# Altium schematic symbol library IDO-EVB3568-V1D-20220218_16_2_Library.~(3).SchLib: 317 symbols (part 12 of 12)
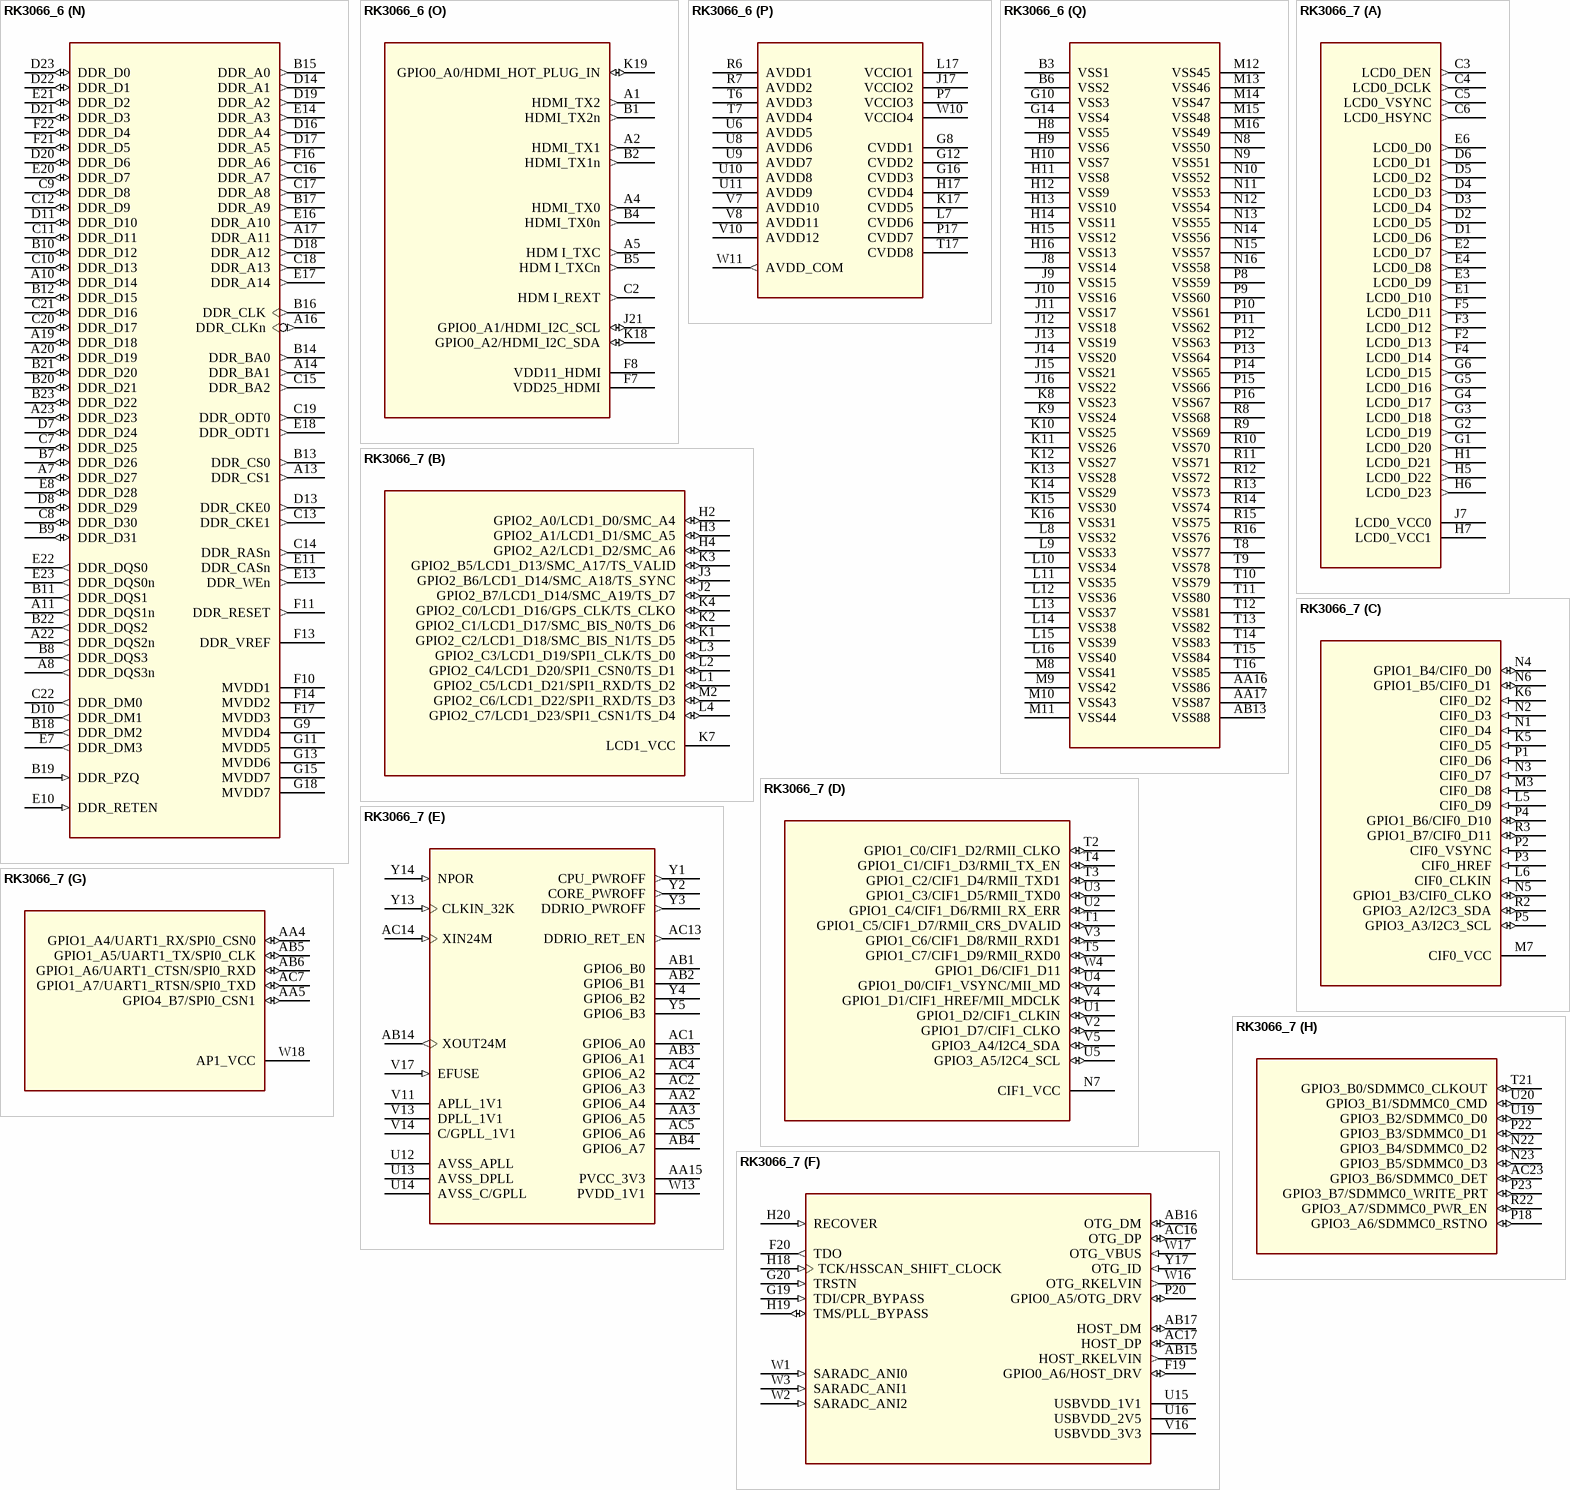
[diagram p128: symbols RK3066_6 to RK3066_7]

## RK3066_6
designator U?
Altium-Right: 160; Altium-Bottom: 120; Altium-Bottom1: 130; Altium-Bottom2: 280; Altium-Right3: 180; Altium-Bottom3: 310; Altium-Bottom4: 270; Altium-Bottom5: 140; Altium-Bottom6: 230; Altium-Bottom7: 530; Altium-Right8: 150; Altium-Bottom8: 250; Altium-Right9: 110; Altium-Bottom9: 170; Altium-Right10: 100; Altium-Bottom10: 470; Altium-Right11: 80; Altium-Bottom11: 350; Altium-Right12: 200; Altium-Bottom12: 190
footprint BGA453
part A pins: C3 LCD0_DEN (out), C4 LCD0_DCLK (out), C5 LCD0_VSYNC (out), C6 LCD0_HSYNC (out), D1 LCD0_D6 (out), D2 LCD0_D5 (out), D3 LCD0_D4 (out), D4 LCD0_D3 (out), D5 LCD0_D2 (out), D6 LCD0_D1 (out), E1 LCD0_D10 (out), E2 LCD0_D7 (out), E3 LCD0_D9 (out), E4 LCD0_D8 (out), E6 LCD0_D0 (out), F2 LCD0_D13 (out), F3 LCD0_D12 (out), F4 LCD0_D14 (out), F5 LCD0_D11 (out), G1 LCD0_D20 (out), G2 LCD0_D19 (out), G3 LCD0_D18 (out), G4 LCD0_D17 (out), G5 LCD0_D16 (out), G6 LCD0_D15 (out), H1 LCD0_D21 (out), H5 LCD0_D22 (out), H6 LCD0_D23 (out), H7 LCD0_VCC1 (power), J7 LCD0_VCC0 (power)
part B pins: H2 GPIO2_A0/LCD1_D0/SMC_A4 (io), H3 GPIO2_A1/LCD1_D1/SMC_A5 (io), H4 GPIO2_A2/LCD1_D2/SMC_A6 (io), J2 GPIO2_B7/LCD1_D14/SMC_A19/TS_D7 (io), J3 GPIO2_B6/LCD1_D14/SMC_A18/TS_SYNC (io), K1 GPIO2_C2/LCD1_D18/SMC_BIS_N1/TS_D5 (io), K2 GPIO2_C1/LCD1_D17/SMC_BIS_N0/TS_D6 (io), K3 GPIO2_B5/LCD1_D13/SMC_A17/TS_VALID (io), K4 GPIO2_C0/LCD1_D16/GPS_CLK/TS_CLKO (io), K7 LCD1_VCC (power), L1 GPIO2_C5/LCD1_D21/SPI1_RXD/TS_D2 (io), L2 GPIO2_C4/LCD1_D20/SPI1_CSN0/TS_D1 (io), L3 GPIO2_C3/LCD1_D19/SPI1_CLK/TS_D0 (io), L4 GPIO2_C7/LCD1_D23/SPI1_CSN1/TS_D4 (io), M2 GPIO2_C6/LCD1_D22/SPI1_RXD/TS_D3 (io)
part C pins: K5 CIF0_D5 (in), K6 CIF0_D2 (in), L5 CIF0_D9 (in), L6 CIF0_CLKIN (in), M3 CIF0_D8 (in), M7 CIF0_VCC (power), N1 CIF0_D4 (in), N2 CIF0_D3 (in), N3 CIF0_D7 (in), N4 GPIO1_B4/CIF0_D0 (io), N5 GPIO1_B3/CIF0_CLKO (io), N6 GPIO1_B5/CIF0_D1 (io), P1 CIF0_D6 (in), P2 CIF0_VSYNC (in), P3 CIF0_HREF (in), P4 GPIO1_B6/CIF0_D10 (io), P5 GPIO3_A3/I2C3_SCL (io), R2 GPIO3_A2/I2C3_SDA (io), R3 GPIO1_B7/CIF0_D11 (io)
part D pins: N7 CIF1_VCC (power), T1 GPIO1_C5/CIF1_D7/RMII_CRS_DVALID (io), T2 GPIO1_C0/CIF1_D2/RMII_CLKO (io), T3 GPIO1_C2/CIF1_D4/RMII_TXD1 (io), T4 GPIO1_C1/CIF1_D3/RMII_TX_EN (io), T5 GPIO1_C7/CIF1_D9/RMII_RXD0 (io), U1 GPIO1_D2/CIF1_CLKIN (io), U2 GPIO1_C4/CIF1_D6/RMII_RX_ERR (io), U3 GPIO1_C3/CIF1_D5/RMII_TXD0 (io), U4 GPIO1_D0/CIF1_VSYNC/MII_MD (io), U5 GPIO3_A5/I2C4_SCL (io), V2 GPIO1_D7/CIF1_CLKO (io), V3 GPIO1_C6/CIF1_D8/RMII_RXD1 (io), V4 GPIO1_D1/CIF1_HREF/MII_MDCLK (io), V5 GPIO3_A4/I2C4_SDA (io), W4 GPIO1_D6/CIF1_D11 (io)
part E pins: AA2 GPIO6_A4, AA3 GPIO6_A5, AA15 PVCC_3V3 (power), AB1 GPIO6_B0, AB2 GPIO6_B1, AB3 GPIO6_A1, AB4 GPIO6_A7, AB14 XOUT24M (out), AC1 GPIO6_A0, AC2 GPIO6_A3, AC4 GPIO6_A2, AC5 GPIO6_A6, AC13 DDRIO_RET_EN (out), AC14 XIN24M (in), U12 AVSS_APLL (power), U13 AVSS_DPLL (power), U14 AVSS_C/GPLL (power), V11 APLL_1V1 (power), V13 DPLL_1V1 (power), V14 C/GPLL_1V1 (power), V17 EFUSE (in), W13 PVDD_1V1 (power), Y1 CPU_PWROFF (out), Y2 CORE_PWROFF (out), Y3 DDRIO_PWROFF (out), Y4 GPIO6_B2, Y5 GPIO6_B3, Y13 CLKIN_32K (in), Y14 NPOR (in)
part F pins: AB15 HOST_RKELVIN (out), AB16 OTG_DM (io), AB17 HOST_DM (io), AC16 OTG_DP (io), AC17 HOST_DP (io), F19 GPIO0_A6/HOST_DRV (io), F20 TDO (out), G19 TDI/CPR_BYPASS (in), G20 TRSTN (in), H18 TCK/HSSCAN_SHIFT_CLOCK (in), H19 TMS/PLL_BYPASS (io), H20 RECOVER (in), P20 GPIO0_A5/OTG_DRV (io), U15 USBVDD_1V1 (power), U16 USBVDD_2V5 (power), V16 USBVDD_3V3 (power), W1 SARADC_ANI0 (in), W2 SARADC_ANI2 (in), W3 SARADC_ANI1 (in), W16 OTG_RKELVIN (out), W17 OTG_VBUS (in), Y17 OTG_ID (in)
part G pins: AA4 GPIO1_A4/UART1_RX/SPI0_CSN0 (io), AA5 GPIO4_B7/SPI0_CSN1 (io), AB5 GPIO1_A5/UART1_TX/SPI0_CLK (io), AB6 GPIO1_A6/UART1_CTSN/SPI0_RXD (io), AC7 GPIO1_A7/UART1_RTSN/SPI0_TXD (io), W18 AP1_VCC (power)
part H pins: AC23 GPIO3_B6/SDMMC0_DET (io), N22 GPIO3_B4/SDMMC0_D2 (io), N23 GPIO3_B5/SDMMC0_D3 (io), P18 GPIO3_A6/SDMMC0_RSTNO (io), P22 GPIO3_B3/SDMMC0_D1 (io), P23 GPIO3_B7/SDMMC0_WRITE_PRT (io), R22 GPIO3_A7/SDMMC0_PWR_EN (io), T21 GPIO3_B0/SDMMC0_CLKOUT (io), U19 GPIO3_B2/SDMMC0_D0 (io), U20 GPIO3_B1/SDMMC0_CMD (io)
part I pins: AA6 GPIO3_C1/SDMMC1_D0 (io), AA7 GPIO3_C2/SDMMC1_D1 (io), AA8 GPIO3_C7/SDMMC1_WRITE_PRT (io), AA9 GPIO1_A1/UART0_SOUT (io), AA10 GPIO0_C3/I2S1_LRCK_TX (io), AA12 GPIO1_A0/UART0_SIN (io), AB7 GPIO3_C0/SDMMC1_CMD (io), AB8 GPIO3_D2/SDMMC1_INT (io), AB9 GPIO0_C1/I2S1_SCLK (io), AB10 GPIO3_D1/SDMMC1_BACKEND (io), AB11 GPIO1_A2/UART0_CTS (io), AC8 GPIO3_C4/SDMMC1_D3 (io), AC10 GPIO3_C3/SDMMC1_D2 (io), AC11 GPIO0_C2/I2S1_LRCK_RX (io), U18 AP0_VCC (power), W6 GPIO3_C6/SDMMC1_DET (io), W7 GPIO0_C4/I2S1_SDI (io), W8 GPIO1_A3/UART0_RTS (io), Y6 GPIO3_C5/SDMMC1_CLKO (io), Y7 GPIO3_D0/SDMMC1_PWR_EN (io), Y8 GPIO0_C5/I2S1_SDO (io), Y11 GPIO0_C0/I2S1_CLK (io)
part J pins: AA11 GPIO4_C0/SMC_D0/TRACE_D0 (io), AA13 GPIO4_C4/SMC_D4/TRACE_D4 (io), AA14 GPIO4_D0/SMC_D8/TRACE_D8 (io), AA18 GPIO4_D3/SMC_D11/TRACE_D11 (io), AA19 GPIO4_D1/SMC_D9/TRACE_D9 (io), AA20 GPIO4_D5/SMC_D13/TRACE_D13 (io), AA21 GPIO0_D5/I2S2_SDO/SMC_A1 (io), AA22 GPIO0_D4/I2S2_SDI/SMC_A0 (io), AB12 GPIO4_C6/SMC_D6/TRACE_D6 (io), AB18 GPIO4_C3/SMC_D3/TRACE_D3 (io), AB19 GPIO4_D6/SMC_D14/TRACE_D14 (io), AB20 GPIO0_C7/SMC_A3/TRACE_CTL (io), AB21 GPIO0_D2/I2S2_LRCK_RX/SMC_OEN (io), AB23 GPIO0_C6/SMC_A2/TRACE_CLK (io), AC19 GPIO4_D7/SMC_D15/TRACE_D15 (io), AC20 GPIO4_D4/SMC_D12/TRACE_D12 (io), AC22 GPIO0_D3/I2S2_LRCK_TX/SMC_ADVN (io), R17 SMC_VCC (power), W14 GPIO4_C7/SMC_D7/TRACE_D7 (io), Y10 GPIO4_C1/SMC_D1/TRACE_D1 (io), Y16 GPIO4_C2/SMC_D2/TRACE_D2 (io), Y18 GPIO4_C5/SMC_D5/TRACE_D5 (io), Y19 GPIO4_D2/SMC_D10/TRACE_D10 (io), Y20 GPIO0_D1/I2S2_SCLK/SMC_WEN (io), Y23 GPIO0_D0/I2S2_CLK/SMC_CSN0 (io)
part K pins: AB22 FLASH_D0/EMMC_D0 (io), M17 FLASH_VCC0 (power), N17 FLASH_VCC1 (power), T18 GPIO4_B0/FLASH_CS1 (io), T19 GPIO4_B1/FLASH_CS2/EMMC_CMD (io), T20 GPIO4_B2/FLASH_CS3/EMMC_RST (io), T22 FLASH_ALE (out), T23 FLASH_CS0 (out), U21 FLASH_WP/EMMC_PWR_EN (out), U22 FLASH_D7/EMMC_D7 (io), U23 FLASH_D6/EMMC_D6 (io), V19 FLASH_RDN (out), V20 FLASH_CLE (out), V21 FLASH_RDY (out), V22 FLASH_D5/EMMC_D5 (io), W20 FLASH_WRN (out), W21 GPIO3_D7/FLASH_DQS/EMMC_CLKO (io), W22 FLASH_D4/EMMC_D4 (io), W23 FLASH_D3/EMMC_D3 (io), Y21 FLASH_D1/EMMC_D1 (io), Y22 FLASH_D2/EMMC_D2 (io)
part L pins: L18 GPIO0_B4/I2S0_D0 (io), L19 GPIO0_B7/I2S0_D3 (io), L21 GPIO1_B2/SPDIF_TX (io), L22 GPIO0_B5/I2S0_D1 (io), N18 GPIO0_B6/I2S0_D2 (io), N20 GPIO0_B2/I2S0_LRCK_RX (io), N21 GPIO0_B1/I2S0_SCLK (io), P19 GPIO0_A7/I2S0_SDI (io), P21 GPIO0_B3/I2S0_LRCK_TX (io), R21 GPIO0_B0/I2S0_CLK (io)
part M pins: G21 GPIO0_A3/PWM0 (io), G22 GPIO0_D6/PWM2 (io), G23 GPIO0_A4/PWM1 (io), H21 GPIO0_D7/PWM3 (io), H22 GPIO3_A1/I2C2_SCL (io), H23 GPIO2_D4/I2C0_SDA (io), J22 GPIO2_D5/I2C0_SCL (io), K20 GPIO3_D6/UART3_RTS (io), K21 GPIO3_D4/UART3_SOUT (io), K22 GPIO3_D3/UART3_SIN (io), K23 GPIO2_D6/I2C1_SDA (io), L20 GPIO3_D5/UART3_CTS (io), L23 GPIO1_B1/UART2_SOUT (io), M21 GPIO2_D7/I2C1_SCL (io), M22 GPIO1_B0/UART2_SIN (io), N19 GPIO3_A0/I2C2_SDA (io)
part N pins: A7 DDR_D27 (io), A8 DDR_DQS3n (out), A10 DDR_D14 (io), A11 DDR_DQS1n (out), A13 DDR_CS1 (out), A14 DDR_BA1 (out), A16 DDR_CLKn (out), A17 DDR_A11 (out), A19 DDR_D18 (io), A20 DDR_D19 (io), A22 DDR_DQS2n (out), A23 DDR_D23 (io), B7 DDR_D26 (io), B8 DDR_DQS3 (out), B9 DDR_D31 (io), B10 DDR_D12 (io), B11 DDR_DQS1 (out), B12 DDR_D15 (io), B13 DDR_CS0 (out), B14 DDR_BA0 (out), B15 DDR_A0 (out), B16 DDR_CLK (out), B17 DDR_A9 (out), B18 DDR_DM2 (out), B19 DDR_PZQ (in), B20 DDR_D21 (io), B21 DDR_D20 (io), B22 DDR_DQS2 (out), B23 DDR_D22 (io), C7 DDR_D25 (io), C8 DDR_D30 (io), C9 DDR_D8 (io), C10 DDR_D13 (io), C11 DDR_D11 (io), C12 DDR_D9 (io), C13 DDR_CKE1 (out), C14 DDR_RASn (out), C15 DDR_BA2 (out), C16 DDR_A7 (out), C17 DDR_A8 (out), C18 DDR_A13 (out), C19 DDR_ODT0 (out), C20 DDR_D17 (io), C21 DDR_D16 (io), C22 DDR_DM0 (out), D7 DDR_D24 (io), D8 DDR_D29 (io), D10 DDR_DM1 (out), D11 DDR_D10 (io), D13 DDR_CKE0 (out), D14 DDR_A1 (out), D16 DDR_A4 (out), D17 DDR_A5 (out), D18 DDR_A12 (out), D19 DDR_A2 (out), D20 DDR_D6 (io), D21 DDR_D3 (io), D22 DDR_D1 (io), D23 DDR_D0 (io), E7 DDR_DM3 (out), E8 DDR_D28 (io), E10 DDR_RETEN (in), E11 DDR_CASn (out), E13 DDR_WEn (out), E14 DDR_A3 (out), E16 DDR_A10 (out), E17 DDR_A14 (out), E18 DDR_ODT1 (out), E20 DDR_D7 (io), E21 DDR_D2 (io), E22 DDR_DQS0 (out), E23 DDR_DQS0n (out), F10 MVDD1 (power), F11 DDR_RESET (out), F13 DDR_VREF (power), F14 MVDD2 (power), F16 DDR_A6 (out), F17 MVDD3 (power), F21 DDR_D5 (io), F22 DDR_D4 (io), G9 MVDD4 (power), G11 MVDD5 (power), G13 MVDD6 (power), G15 MVDD7 (power), G18 MVDD7 (power)
part O pins: A1 HDMI_TX2 (out), A2 HDMI_TX1 (out), A4 HDMI_TX0 (out), A5 HDM I_TXC (out), B1 HDMI_TX2n (out), B2 HDMI_TX1n (out), B4 HDMI_TX0n (out), B5 HDM I_TXCn (out), C2 HDM I_REXT (out), F7 VDD25_HDMI (power), F8 VDD11_HDMI (power), J21 GPIO0_A1/HDMI_I2C_SCL (io), K18 GPIO0_A2/HDMI_I2C_SDA (io), K19 GPIO0_A0/HDMI_HOT_PLUG_IN (io)
part P pins: G8 CVDD1 (power), G12 CVDD2 (power), G16 CVDD3 (power), H17 CVDD4 (power), J17 VCCIO2 (power), K17 CVDD5 (power), L7 CVDD6 (power), L17 VCCIO1 (power), P7 VCCIO3 (power), P17 CVDD7 (power), R6 AVDD1 (power), R7 AVDD2 (power), T6 AVDD3 (power), T7 AVDD4 (power), T17 CVDD8 (power), U6 AVDD5 (power), U8 AVDD6 (power), U9 AVDD7 (power), U10 AVDD8 (power), U11 AVDD9 (power), V7 AVDD10 (power), V8 AVDD11 (power), V10 AVDD12 (power), W10 VCCIO4 (power), W11 AVDD_COM (out)
part Q pins: AA16 VSS86 (power), AA17 VSS87 (power), AB13 VSS88 (power), B3 VSS1 (power), B6 VSS2 (power), G10 VSS3 (power), G14 VSS4 (power), H8 VSS5 (power), H9 VSS6 (power), H10 VSS7 (power), H11 VSS8 (power), H12 VSS9 (power), H13 VSS10 (power), H14 VSS11 (power), H15 VSS12 (power), H16 VSS13 (power), J8 VSS14 (power), J9 VSS15 (power), J10 VSS16 (power), J11 VSS17 (power), J12 VSS18 (power), J13 VSS19 (power), J14 VSS20 (power), J15 VSS21 (power), J16 VSS22 (power), K8 VSS23 (power), K9 VSS24 (power), K10 VSS25 (power), K11 VSS26 (power), K12 VSS27 (power), K13 VSS28 (power), K14 VSS29 (power), K15 VSS30 (power), K16 VSS31 (power), L8 VSS32 (power), L9 VSS33 (power), L10 VSS34 (power), L11 VSS35 (power), L12 VSS36 (power), L13 VSS37 (power), L14 VSS38 (power), L15 VSS39 (power), L16 VSS40 (power), M8 VSS41 (power), M9 VSS42 (power), M10 VSS43 (power), M11 VSS44 (power), M12 VSS45 (power), M13 VSS46 (power), M14 VSS47 (power), M15 VSS48 (power), M16 VSS49 (power), N8 VSS50 (power), N9 VSS51 (power), N10 VSS52 (power), N11 VSS53 (power), N12 VSS54 (power), N13 VSS55 (power), N14 VSS56 (power), N15 VSS57 (power), N16 VSS58 (power), P8 VSS59 (power), P9 VSS60 (power), P10 VSS61 (power), P11 VSS62 (power), P12 VSS63 (power), P13 VSS64 (power), P14 VSS65 (power), P15 VSS66 (power), P16 VSS67 (power), R8 VSS68 (power), R9 VSS69 (power), R10 VSS70 (power), R11 VSS71 (power), R12 VSS72 (power), R13 VSS73 (power), R14 VSS74 (power), R15 VSS75 (power), R16 VSS76 (power), T8 VSS77 (power), T9 VSS78 (power), T10 VSS79 (power), T11 VSS80 (power), T12 VSS81 (power), T13 VSS82 (power), T14 VSS83 (power), T15 VSS84 (power), T16 VSS85 (power)

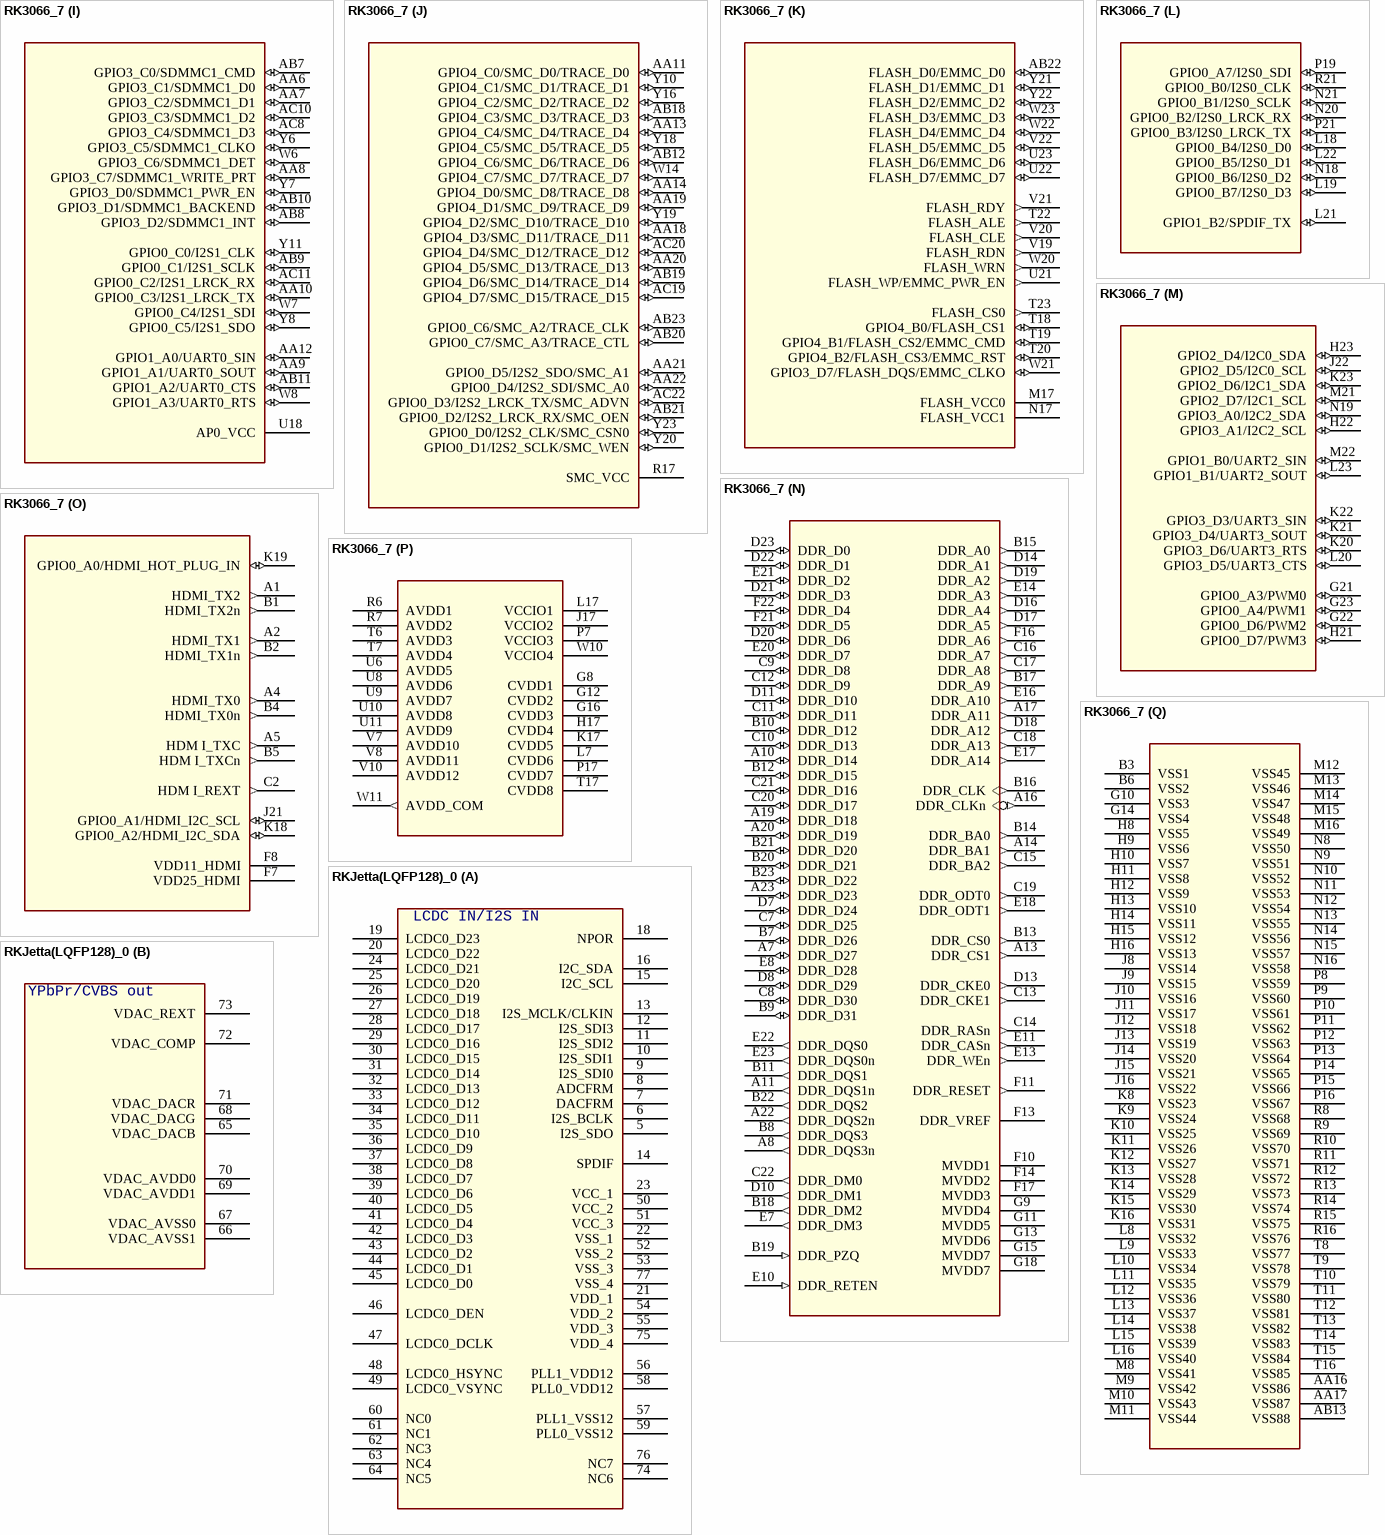
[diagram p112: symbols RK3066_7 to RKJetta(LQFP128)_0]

## RK3066_7
designator U?
Altium-Right: 160; Altium-Bottom: 130; Altium-Bottom1: 280; Altium-Right2: 180; Altium-Bottom2: 310; Altium-Bottom3: 270; Altium-Right4: 120; Altium-Bottom4: 140; Altium-Bottom5: 230; Altium-Bottom6: 530; Altium-Right7: 150; Altium-Bottom7: 250; Altium-Right8: 110; Altium-Bottom8: 170; Altium-Right9: 100; Altium-Bottom9: 470; Altium-Right10: 80; Altium-Bottom10: 350; Altium-Right11: 200; Altium-Bottom11: 190
footprint BGA453
part A pins: C3 LCD0_DEN (out), C4 LCD0_DCLK (out), C5 LCD0_VSYNC (out), C6 LCD0_HSYNC (out), D1 LCD0_D6 (out), D2 LCD0_D5 (out), D3 LCD0_D4 (out), D4 LCD0_D3 (out), D5 LCD0_D2 (out), D6 LCD0_D1 (out), E1 LCD0_D10 (out), E2 LCD0_D7 (out), E3 LCD0_D9 (out), E4 LCD0_D8 (out), E6 LCD0_D0 (out), F2 LCD0_D13 (out), F3 LCD0_D12 (out), F4 LCD0_D14 (out), F5 LCD0_D11 (out), G1 LCD0_D20 (out), G2 LCD0_D19 (out), G3 LCD0_D18 (out), G4 LCD0_D17 (out), G5 LCD0_D16 (out), G6 LCD0_D15 (out), H1 LCD0_D21 (out), H5 LCD0_D22 (out), H6 LCD0_D23 (out), H7 LCD0_VCC1 (power), J7 LCD0_VCC0 (power)
part B pins: H2 GPIO2_A0/LCD1_D0/SMC_A4 (io), H3 GPIO2_A1/LCD1_D1/SMC_A5 (io), H4 GPIO2_A2/LCD1_D2/SMC_A6 (io), J2 GPIO2_B7/LCD1_D14/SMC_A19/TS_D7 (io), J3 GPIO2_B6/LCD1_D14/SMC_A18/TS_SYNC (io), K1 GPIO2_C2/LCD1_D18/SMC_BIS_N1/TS_D5 (io), K2 GPIO2_C1/LCD1_D17/SMC_BIS_N0/TS_D6 (io), K3 GPIO2_B5/LCD1_D13/SMC_A17/TS_VALID (io), K4 GPIO2_C0/LCD1_D16/GPS_CLK/TS_CLKO (io), K7 LCD1_VCC (power), L1 GPIO2_C5/LCD1_D21/SPI1_RXD/TS_D2 (io), L2 GPIO2_C4/LCD1_D20/SPI1_CSN0/TS_D1 (io), L3 GPIO2_C3/LCD1_D19/SPI1_CLK/TS_D0 (io), L4 GPIO2_C7/LCD1_D23/SPI1_CSN1/TS_D4 (io), M2 GPIO2_C6/LCD1_D22/SPI1_RXD/TS_D3 (io)
part C pins: K5 CIF0_D5 (in), K6 CIF0_D2 (in), L5 CIF0_D9 (in), L6 CIF0_CLKIN (in), M3 CIF0_D8 (in), M7 CIF0_VCC (power), N1 CIF0_D4 (in), N2 CIF0_D3 (in), N3 CIF0_D7 (in), N4 GPIO1_B4/CIF0_D0 (io), N5 GPIO1_B3/CIF0_CLKO (io), N6 GPIO1_B5/CIF0_D1 (io), P1 CIF0_D6 (in), P2 CIF0_VSYNC (in), P3 CIF0_HREF (in), P4 GPIO1_B6/CIF0_D10 (io), P5 GPIO3_A3/I2C3_SCL (io), R2 GPIO3_A2/I2C3_SDA (io), R3 GPIO1_B7/CIF0_D11 (io)
part D pins: N7 CIF1_VCC (power), T1 GPIO1_C5/CIF1_D7/RMII_CRS_DVALID (io), T2 GPIO1_C0/CIF1_D2/RMII_CLKO (io), T3 GPIO1_C2/CIF1_D4/RMII_TXD1 (io), T4 GPIO1_C1/CIF1_D3/RMII_TX_EN (io), T5 GPIO1_C7/CIF1_D9/RMII_RXD0 (io), U1 GPIO1_D2/CIF1_CLKIN (io), U2 GPIO1_C4/CIF1_D6/RMII_RX_ERR (io), U3 GPIO1_C3/CIF1_D5/RMII_TXD0 (io), U4 GPIO1_D0/CIF1_VSYNC/MII_MD (io), U5 GPIO3_A5/I2C4_SCL (io), V2 GPIO1_D7/CIF1_CLKO (io), V3 GPIO1_C6/CIF1_D8/RMII_RXD1 (io), V4 GPIO1_D1/CIF1_HREF/MII_MDCLK (io), V5 GPIO3_A4/I2C4_SDA (io), W4 GPIO1_D6/CIF1_D11 (io)
part E pins: AA2 GPIO6_A4, AA3 GPIO6_A5, AA15 PVCC_3V3 (power), AB1 GPIO6_B0, AB2 GPIO6_B1, AB3 GPIO6_A1, AB4 GPIO6_A7, AB14 XOUT24M (out), AC1 GPIO6_A0, AC2 GPIO6_A3, AC4 GPIO6_A2, AC5 GPIO6_A6, AC13 DDRIO_RET_EN (out), AC14 XIN24M (in), U12 AVSS_APLL (power), U13 AVSS_DPLL (power), U14 AVSS_C/GPLL (power), V11 APLL_1V1 (power), V13 DPLL_1V1 (power), V14 C/GPLL_1V1 (power), V17 EFUSE (in), W13 PVDD_1V1 (power), Y1 CPU_PWROFF (out), Y2 CORE_PWROFF (out), Y3 DDRIO_PWROFF (out), Y4 GPIO6_B2, Y5 GPIO6_B3, Y13 CLKIN_32K (in), Y14 NPOR (in)
part F pins: AB15 HOST_RKELVIN (out), AB16 OTG_DM (io), AB17 HOST_DM (io), AC16 OTG_DP (io), AC17 HOST_DP (io), F19 GPIO0_A6/HOST_DRV (io), F20 TDO (out), G19 TDI/CPR_BYPASS (in), G20 TRSTN (in), H18 TCK/HSSCAN_SHIFT_CLOCK (in), H19 TMS/PLL_BYPASS (io), H20 RECOVER (in), P20 GPIO0_A5/OTG_DRV (io), U15 USBVDD_1V1 (power), U16 USBVDD_2V5 (power), V16 USBVDD_3V3 (power), W1 SARADC_ANI0 (in), W2 SARADC_ANI2 (in), W3 SARADC_ANI1 (in), W16 OTG_RKELVIN (out), W17 OTG_VBUS (in), Y17 OTG_ID (in)
part G pins: AA4 GPIO1_A4/UART1_RX/SPI0_CSN0 (io), AA5 GPIO4_B7/SPI0_CSN1 (io), AB5 GPIO1_A5/UART1_TX/SPI0_CLK (io), AB6 GPIO1_A6/UART1_CTSN/SPI0_RXD (io), AC7 GPIO1_A7/UART1_RTSN/SPI0_TXD (io), W18 AP1_VCC (power)
part H pins: AC23 GPIO3_B6/SDMMC0_DET (io), N22 GPIO3_B4/SDMMC0_D2 (io), N23 GPIO3_B5/SDMMC0_D3 (io), P18 GPIO3_A6/SDMMC0_RSTNO (io), P22 GPIO3_B3/SDMMC0_D1 (io), P23 GPIO3_B7/SDMMC0_WRITE_PRT (io), R22 GPIO3_A7/SDMMC0_PWR_EN (io), T21 GPIO3_B0/SDMMC0_CLKOUT (io), U19 GPIO3_B2/SDMMC0_D0 (io), U20 GPIO3_B1/SDMMC0_CMD (io)
part I pins: AA6 GPIO3_C1/SDMMC1_D0 (io), AA7 GPIO3_C2/SDMMC1_D1 (io), AA8 GPIO3_C7/SDMMC1_WRITE_PRT (io), AA9 GPIO1_A1/UART0_SOUT (io), AA10 GPIO0_C3/I2S1_LRCK_TX (io), AA12 GPIO1_A0/UART0_SIN (io), AB7 GPIO3_C0/SDMMC1_CMD (io), AB8 GPIO3_D2/SDMMC1_INT (io), AB9 GPIO0_C1/I2S1_SCLK (io), AB10 GPIO3_D1/SDMMC1_BACKEND (io), AB11 GPIO1_A2/UART0_CTS (io), AC8 GPIO3_C4/SDMMC1_D3 (io), AC10 GPIO3_C3/SDMMC1_D2 (io), AC11 GPIO0_C2/I2S1_LRCK_RX (io), U18 AP0_VCC (power), W6 GPIO3_C6/SDMMC1_DET (io), W7 GPIO0_C4/I2S1_SDI (io), W8 GPIO1_A3/UART0_RTS (io), Y6 GPIO3_C5/SDMMC1_CLKO (io), Y7 GPIO3_D0/SDMMC1_PWR_EN (io), Y8 GPIO0_C5/I2S1_SDO (io), Y11 GPIO0_C0/I2S1_CLK (io)
part J pins: AA11 GPIO4_C0/SMC_D0/TRACE_D0 (io), AA13 GPIO4_C4/SMC_D4/TRACE_D4 (io), AA14 GPIO4_D0/SMC_D8/TRACE_D8 (io), AA18 GPIO4_D3/SMC_D11/TRACE_D11 (io), AA19 GPIO4_D1/SMC_D9/TRACE_D9 (io), AA20 GPIO4_D5/SMC_D13/TRACE_D13 (io), AA21 GPIO0_D5/I2S2_SDO/SMC_A1 (io), AA22 GPIO0_D4/I2S2_SDI/SMC_A0 (io), AB12 GPIO4_C6/SMC_D6/TRACE_D6 (io), AB18 GPIO4_C3/SMC_D3/TRACE_D3 (io), AB19 GPIO4_D6/SMC_D14/TRACE_D14 (io), AB20 GPIO0_C7/SMC_A3/TRACE_CTL (io), AB21 GPIO0_D2/I2S2_LRCK_RX/SMC_OEN (io), AB23 GPIO0_C6/SMC_A2/TRACE_CLK (io), AC19 GPIO4_D7/SMC_D15/TRACE_D15 (io), AC20 GPIO4_D4/SMC_D12/TRACE_D12 (io), AC22 GPIO0_D3/I2S2_LRCK_TX/SMC_ADVN (io), R17 SMC_VCC (power), W14 GPIO4_C7/SMC_D7/TRACE_D7 (io), Y10 GPIO4_C1/SMC_D1/TRACE_D1 (io), Y16 GPIO4_C2/SMC_D2/TRACE_D2 (io), Y18 GPIO4_C5/SMC_D5/TRACE_D5 (io), Y19 GPIO4_D2/SMC_D10/TRACE_D10 (io), Y20 GPIO0_D1/I2S2_SCLK/SMC_WEN (io), Y23 GPIO0_D0/I2S2_CLK/SMC_CSN0 (io)
part K pins: AB22 FLASH_D0/EMMC_D0 (io), M17 FLASH_VCC0 (power), N17 FLASH_VCC1 (power), T18 GPIO4_B0/FLASH_CS1 (io), T19 GPIO4_B1/FLASH_CS2/EMMC_CMD (io), T20 GPIO4_B2/FLASH_CS3/EMMC_RST (io), T22 FLASH_ALE (out), T23 FLASH_CS0 (out), U21 FLASH_WP/EMMC_PWR_EN (out), U22 FLASH_D7/EMMC_D7 (io), U23 FLASH_D6/EMMC_D6 (io), V19 FLASH_RDN (out), V20 FLASH_CLE (out), V21 FLASH_RDY (out), V22 FLASH_D5/EMMC_D5 (io), W20 FLASH_WRN (out), W21 GPIO3_D7/FLASH_DQS/EMMC_CLKO (io), W22 FLASH_D4/EMMC_D4 (io), W23 FLASH_D3/EMMC_D3 (io), Y21 FLASH_D1/EMMC_D1 (io), Y22 FLASH_D2/EMMC_D2 (io)
part L pins: L18 GPIO0_B4/I2S0_D0 (io), L19 GPIO0_B7/I2S0_D3 (io), L21 GPIO1_B2/SPDIF_TX (io), L22 GPIO0_B5/I2S0_D1 (io), N18 GPIO0_B6/I2S0_D2 (io), N20 GPIO0_B2/I2S0_LRCK_RX (io), N21 GPIO0_B1/I2S0_SCLK (io), P19 GPIO0_A7/I2S0_SDI (io), P21 GPIO0_B3/I2S0_LRCK_TX (io), R21 GPIO0_B0/I2S0_CLK (io)
part M pins: G21 GPIO0_A3/PWM0 (io), G22 GPIO0_D6/PWM2 (io), G23 GPIO0_A4/PWM1 (io), H21 GPIO0_D7/PWM3 (io), H22 GPIO3_A1/I2C2_SCL (io), H23 GPIO2_D4/I2C0_SDA (io), J22 GPIO2_D5/I2C0_SCL (io), K20 GPIO3_D6/UART3_RTS (io), K21 GPIO3_D4/UART3_SOUT (io), K22 GPIO3_D3/UART3_SIN (io), K23 GPIO2_D6/I2C1_SDA (io), L20 GPIO3_D5/UART3_CTS (io), L23 GPIO1_B1/UART2_SOUT (io), M21 GPIO2_D7/I2C1_SCL (io), M22 GPIO1_B0/UART2_SIN (io), N19 GPIO3_A0/I2C2_SDA (io)
part N pins: A7 DDR_D27 (io), A8 DDR_DQS3n (out), A10 DDR_D14 (io), A11 DDR_DQS1n (out), A13 DDR_CS1 (out), A14 DDR_BA1 (out), A16 DDR_CLKn (out), A17 DDR_A11 (out), A19 DDR_D18 (io), A20 DDR_D19 (io), A22 DDR_DQS2n (out), A23 DDR_D23 (io), B7 DDR_D26 (io), B8 DDR_DQS3 (out), B9 DDR_D31 (io), B10 DDR_D12 (io), B11 DDR_DQS1 (out), B12 DDR_D15 (io), B13 DDR_CS0 (out), B14 DDR_BA0 (out), B15 DDR_A0 (out), B16 DDR_CLK (out), B17 DDR_A9 (out), B18 DDR_DM2 (out), B19 DDR_PZQ (in), B20 DDR_D21 (io), B21 DDR_D20 (io), B22 DDR_DQS2 (out), B23 DDR_D22 (io), C7 DDR_D25 (io), C8 DDR_D30 (io), C9 DDR_D8 (io), C10 DDR_D13 (io), C11 DDR_D11 (io), C12 DDR_D9 (io), C13 DDR_CKE1 (out), C14 DDR_RASn (out), C15 DDR_BA2 (out), C16 DDR_A7 (out), C17 DDR_A8 (out), C18 DDR_A13 (out), C19 DDR_ODT0 (out), C20 DDR_D17 (io), C21 DDR_D16 (io), C22 DDR_DM0 (out), D7 DDR_D24 (io), D8 DDR_D29 (io), D10 DDR_DM1 (out), D11 DDR_D10 (io), D13 DDR_CKE0 (out), D14 DDR_A1 (out), D16 DDR_A4 (out), D17 DDR_A5 (out), D18 DDR_A12 (out), D19 DDR_A2 (out), D20 DDR_D6 (io), D21 DDR_D3 (io), D22 DDR_D1 (io), D23 DDR_D0 (io), E7 DDR_DM3 (out), E8 DDR_D28 (io), E10 DDR_RETEN (in), E11 DDR_CASn (out), E13 DDR_WEn (out), E14 DDR_A3 (out), E16 DDR_A10 (out), E17 DDR_A14 (out), E18 DDR_ODT1 (out), E20 DDR_D7 (io), E21 DDR_D2 (io), E22 DDR_DQS0 (out), E23 DDR_DQS0n (out), F10 MVDD1 (power), F11 DDR_RESET (out), F13 DDR_VREF (power), F14 MVDD2 (power), F16 DDR_A6 (out), F17 MVDD3 (power), F21 DDR_D5 (io), F22 DDR_D4 (io), G9 MVDD4 (power), G11 MVDD5 (power), G13 MVDD6 (power), G15 MVDD7 (power), G18 MVDD7 (power)
part O pins: A1 HDMI_TX2 (out), A2 HDMI_TX1 (out), A4 HDMI_TX0 (out), A5 HDM I_TXC (out), B1 HDMI_TX2n (out), B2 HDMI_TX1n (out), B4 HDMI_TX0n (out), B5 HDM I_TXCn (out), C2 HDM I_REXT (out), F7 VDD25_HDMI (power), F8 VDD11_HDMI (power), J21 GPIO0_A1/HDMI_I2C_SCL (io), K18 GPIO0_A2/HDMI_I2C_SDA (io), K19 GPIO0_A0/HDMI_HOT_PLUG_IN (io)
part P pins: G8 CVDD1 (power), G12 CVDD2 (power), G16 CVDD3 (power), H17 CVDD4 (power), J17 VCCIO2 (power), K17 CVDD5 (power), L7 CVDD6 (power), L17 VCCIO1 (power), P7 VCCIO3 (power), P17 CVDD7 (power), R6 AVDD1 (power), R7 AVDD2 (power), T6 AVDD3 (power), T7 AVDD4 (power), T17 CVDD8 (power), U6 AVDD5 (power), U8 AVDD6 (power), U9 AVDD7 (power), U10 AVDD8 (power), U11 AVDD9 (power), V7 AVDD10 (power), V8 AVDD11 (power), V10 AVDD12 (power), W10 VCCIO4 (power), W11 AVDD_COM (out)
part Q pins: AA16 VSS86 (power), AA17 VSS87 (power), AB13 VSS88 (power), B3 VSS1 (power), B6 VSS2 (power), G10 VSS3 (power), G14 VSS4 (power), H8 VSS5 (power), H9 VSS6 (power), H10 VSS7 (power), H11 VSS8 (power), H12 VSS9 (power), H13 VSS10 (power), H14 VSS11 (power), H15 VSS12 (power), H16 VSS13 (power), J8 VSS14 (power), J9 VSS15 (power), J10 VSS16 (power), J11 VSS17 (power), J12 VSS18 (power), J13 VSS19 (power), J14 VSS20 (power), J15 VSS21 (power), J16 VSS22 (power), K8 VSS23 (power), K9 VSS24 (power), K10 VSS25 (power), K11 VSS26 (power), K12 VSS27 (power), K13 VSS28 (power), K14 VSS29 (power), K15 VSS30 (power), K16 VSS31 (power), L8 VSS32 (power), L9 VSS33 (power), L10 VSS34 (power), L11 VSS35 (power), L12 VSS36 (power), L13 VSS37 (power), L14 VSS38 (power), L15 VSS39 (power), L16 VSS40 (power), M8 VSS41 (power), M9 VSS42 (power), M10 VSS43 (power), M11 VSS44 (power), M12 VSS45 (power), M13 VSS46 (power), M14 VSS47 (power), M15 VSS48 (power), M16 VSS49 (power), N8 VSS50 (power), N9 VSS51 (power), N10 VSS52 (power), N11 VSS53 (power), N12 VSS54 (power), N13 VSS55 (power), N14 VSS56 (power), N15 VSS57 (power), N16 VSS58 (power), P8 VSS59 (power), P9 VSS60 (power), P10 VSS61 (power), P11 VSS62 (power), P12 VSS63 (power), P13 VSS64 (power), P14 VSS65 (power), P15 VSS66 (power), P16 VSS67 (power), R8 VSS68 (power), R9 VSS69 (power), R10 VSS70 (power), R11 VSS71 (power), R12 VSS72 (power), R13 VSS73 (power), R14 VSS74 (power), R15 VSS75 (power), R16 VSS76 (power), T8 VSS77 (power), T9 VSS78 (power), T10 VSS79 (power), T11 VSS80 (power), T12 VSS81 (power), T13 VSS82 (power), T14 VSS83 (power), T15 VSS84 (power), T16 VSS85 (power)

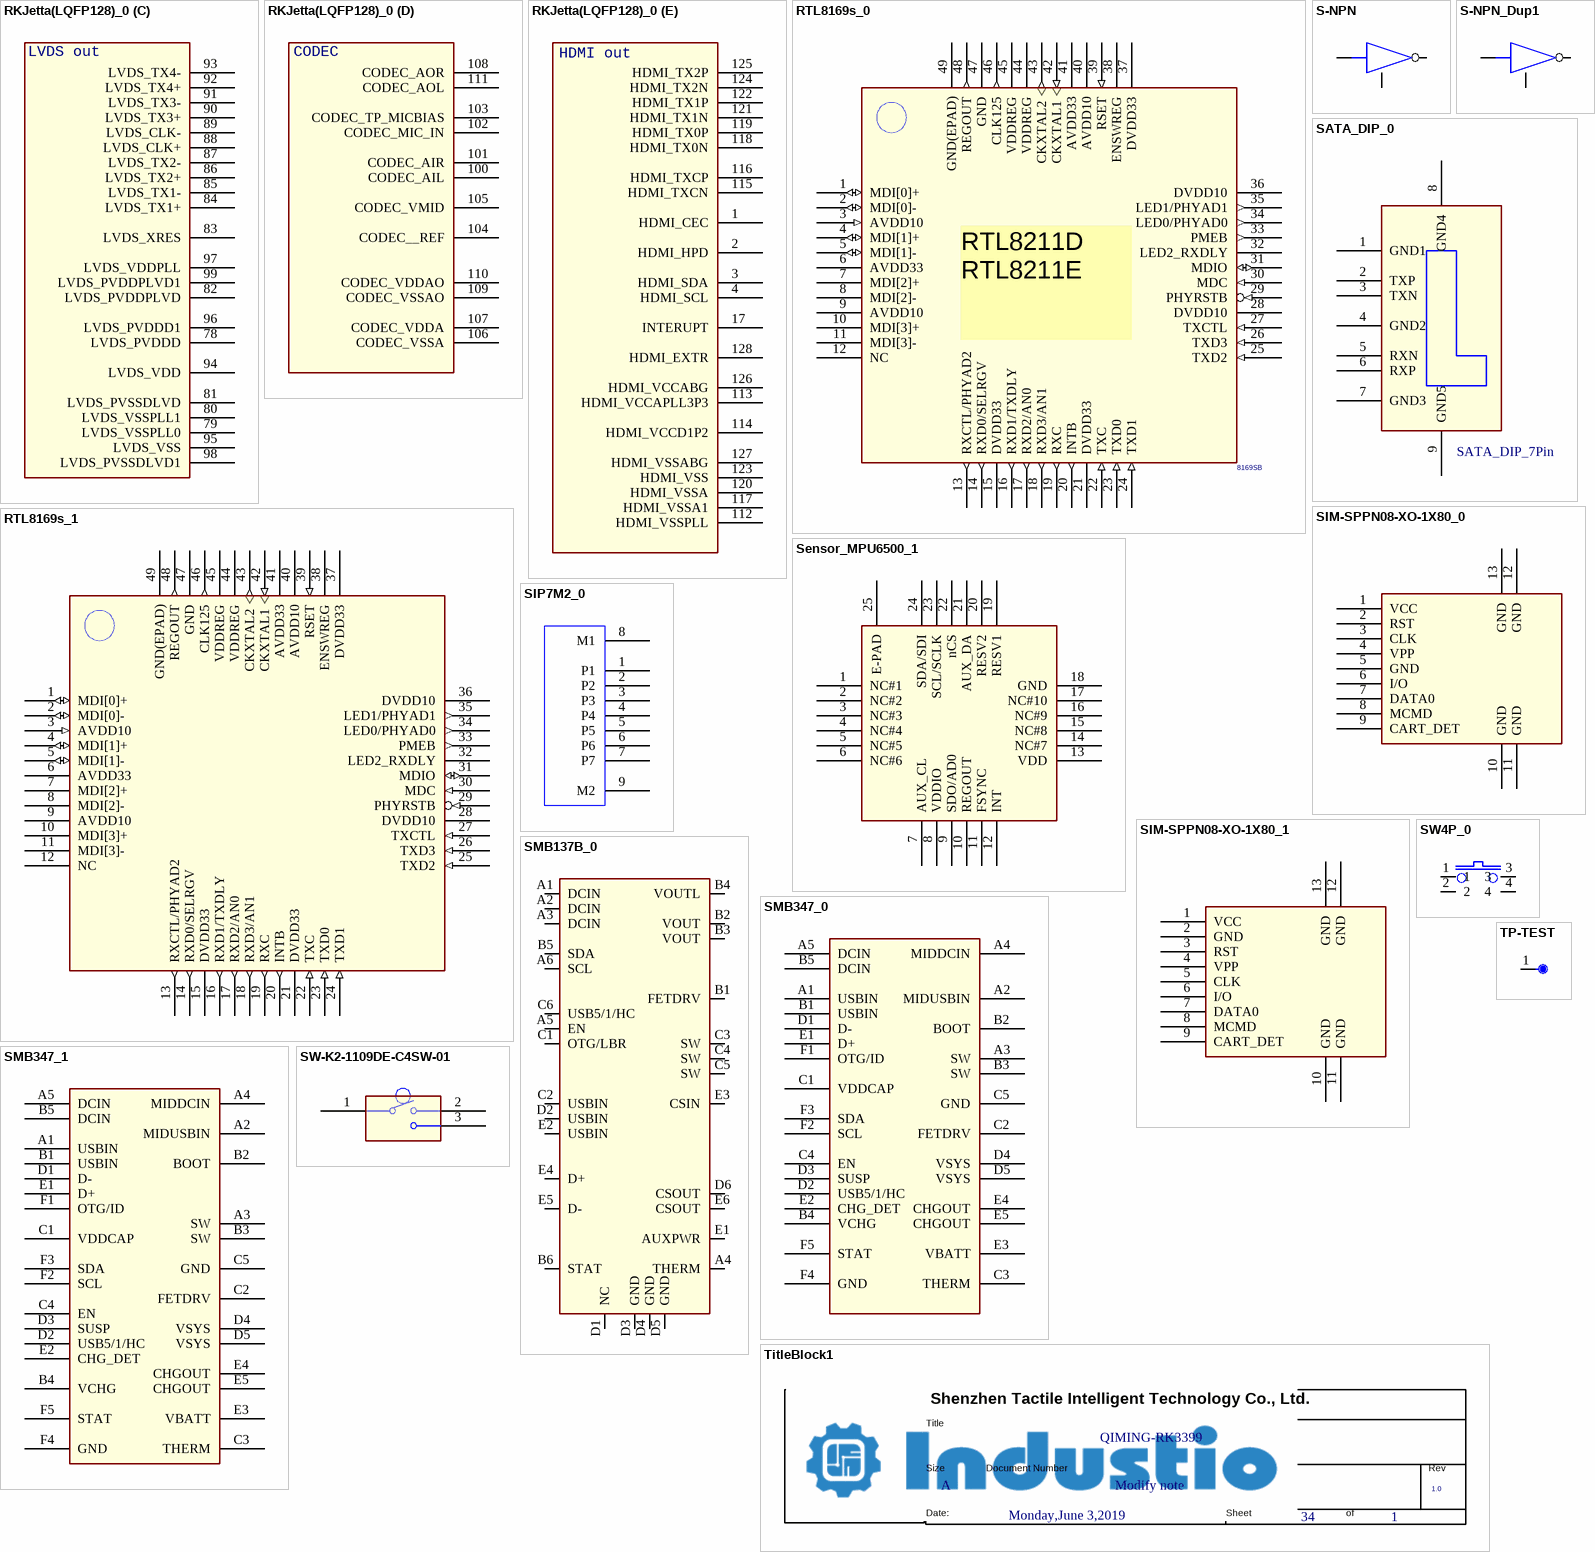
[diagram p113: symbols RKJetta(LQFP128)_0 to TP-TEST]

## RKJetta(LQFP128)_0
designator U?
Altium-Right: 150; Altium-Bottom: 400; Altium-Right1: 120; Altium-Bottom1: 190; Altium-Right2: 110; Altium-Bottom2: 290; Altium-Bottom3: 220; Altium-Bottom4: 340
footprint LQFP128
part A pins: 5 I2S_SDO, 6 I2S_BCLK, 7 DACFRM, 8 ADCFRM, 9 I2S_SDI0, 10 I2S_SDI1, 11 I2S_SDI2, 12 I2S_SDI3, 13 I2S_MCLK/CLKIN, 14 SPDIF, 15 I2C_SCL, 16 I2C_SDA, 18 NPOR, 19 LCDC0_D23, 20 LCDC0_D22, 21 VDD_1, 22 VSS_1, 23 VCC_1, 24 LCDC0_D21, 25 LCDC0_D20, 26 LCDC0_D19, 27 LCDC0_D18, 28 LCDC0_D17, 29 LCDC0_D16, 30 LCDC0_D15, 31 LCDC0_D14, 32 LCDC0_D13, 33 LCDC0_D12, 34 LCDC0_D11, 35 LCDC0_D10, 36 LCDC0_D9, 37 LCDC0_D8, 38 LCDC0_D7, 39 LCDC0_D6, 40 LCDC0_D5, 41 LCDC0_D4, 42 LCDC0_D3, 43 LCDC0_D2, 44 LCDC0_D1, 45 LCDC0_D0, 46 LCDC0_DEN, 47 LCDC0_DCLK, 48 LCDC0_HSYNC, 49 LCDC0_VSYNC, 50 VCC_2, 51 VCC_3, 52 VSS_2, 53 VSS_3, 54 VDD_2, 55 VDD_3, 56 PLL1_VDD12, 57 PLL1_VSS12, 58 PLL0_VDD12, 59 PLL0_VSS12, 60 NC0, 61 NC1, 62 NC3, 63 NC4, 64 NC5, 74 NC6, 75 VDD_4, 76 NC7, 77 VSS_4
part B pins: 65 VDAC_DACB, 66 VDAC_AVSS1, 67 VDAC_AVSS0, 68 VDAC_DACG, 69 VDAC_AVDD1, 70 VDAC_AVDD0, 71 VDAC_DACR, 72 VDAC_COMP, 73 VDAC_REXT
part C pins: 78 LVDS_PVDDD, 79 LVDS_VSSPLL0, 80 LVDS_VSSPLL1, 81 LVDS_PVSSDLVD, 82 LVDS_PVDDPLVD, 83 LVDS_XRES, 84 LVDS_TX1+, 85 LVDS_TX1-, 86 LVDS_TX2+, 87 LVDS_TX2-, 88 LVDS_CLK+, 89 LVDS_CLK-, 90 LVDS_TX3+, 91 LVDS_TX3-, 92 LVDS_TX4+, 93 LVDS_TX4-, 94 LVDS_VDD, 95 LVDS_VSS, 96 LVDS_PVDDD1, 97 LVDS_VDDPLL, 98 LVDS_PVSSDLVD1, 99 LVDS_PVDDPLVD1
part D pins: 100 CODEC_AIL, 101 CODEC_AIR, 102 CODEC_MIC_IN, 103 CODEC_TP_MICBIAS, 104 CODEC__REF, 105 CODEC_VMID, 106 CODEC_VSSA, 107 CODEC_VDDA, 108 CODEC_AOR, 109 CODEC_VSSAO, 110 CODEC_VDDAO, 111 CODEC_AOL
part E pins: 1 HDMI_CEC, 2 HDMI_HPD, 3 HDMI_SDA, 4 HDMI_SCL, 17 INTERUPT, 112 HDMI_VSSPLL, 113 HDMI_VCCAPLL3P3, 114 HDMI_VCCD1P2, 115 HDMI_TXCN, 116 HDMI_TXCP, 117 HDMI_VSSA1, 118 HDMI_TX0N, 119 HDMI_TX0P, 120 HDMI_VSSA, 121 HDMI_TX1N, 122 HDMI_TX1P, 123 HDMI_VSS, 124 HDMI_TX2N, 125 HDMI_TX2P, 126 HDMI_VCCABG, 127 HDMI_VSSABG, 128 HDMI_EXTR

## RTL8169s_0
designator U?, comment 8169SB
Altium-Right: 250
pins: 1 MDI[0]+ (io), 2 MDI[0]- (io), 3 AVDD10 (in), 4 MDI[1]+ (io), 5 MDI[1]- (io), 6 AVDD33 (power), 7 MDI[2]+, 8 MDI[2]-, 9 AVDD10 (power), 10 MDI[3]+, 11 MDI[3]-, 12 NC, 13 RXCTL/PHYAD2 (out), 14 RXD0/SELRGV (out), 15 DVDD33 (power), 16 RXD1/TXDLY (out), 17 RXD2/AN0 (out), 18 RXD3/AN1 (out), 19 RXC (out), 20 INTB (out), 21 DVDD33 (power), 22 TXC (in), 23 TXD0 (in), 24 TXD1 (in), 25 TXD2 (in), 26 TXD3 (in), 27 TXCTL (in), 28 DVDD10 (power), 29 PHYRSTB (in), 30 MDC (in), 31 MDIO (io), 32 LED2_RXDLY, 33 PMEB (out), 34 LED0/PHYAD0 (out), 35 LED1/PHYAD1 (out), 36 DVDD10 (power), 37 DVDD33 (power), 38 ENSWREG, 39 RSET (in), 40 AVDD10 (power), 41 AVDD33 (power), 42 CKXTAL1 (in), 43 CKXTAL2 (out), 44 VDDREG (power), 45 VDDREG (power), 46 CLK125 (out), 47 GND, 48 REGOUT (out), 49 GND(EPAD)

## RTL8169s_1
designator U?
Altium-Right: 250
pins: 1 MDI[0]+ (io), 2 MDI[0]- (io), 3 AVDD10 (in), 4 MDI[1]+ (io), 5 MDI[1]- (io), 6 AVDD33 (power), 7 MDI[2]+, 8 MDI[2]-, 9 AVDD10 (power), 10 MDI[3]+, 11 MDI[3]-, 12 NC, 13 RXCTL/PHYAD2 (out), 14 RXD0/SELRGV (out), 15 DVDD33 (power), 16 RXD1/TXDLY (out), 17 RXD2/AN0 (out), 18 RXD3/AN1 (out), 19 RXC (out), 20 INTB (out), 21 DVDD33 (power), 22 TXC (in), 23 TXD0 (in), 24 TXD1 (in), 25 TXD2 (in), 26 TXD3 (in), 27 TXCTL (in), 28 DVDD10 (power), 29 PHYRSTB (in), 30 MDC (in), 31 MDIO (io), 32 LED2_RXDLY, 33 PMEB (out), 34 LED0/PHYAD0 (out), 35 LED1/PHYAD1 (out), 36 DVDD10 (power), 37 DVDD33 (power), 38 ENSWREG, 39 RSET (in), 40 AVDD10 (power), 41 AVDD33 (power), 42 CKXTAL1 (in), 43 CKXTAL2 (out), 44 VDDREG (power), 45 VDDREG (power), 46 CLK125 (out), 47 GND, 48 REGOUT (out), 49 GND(EPAD)

## S-NPN
designator Q?
Altium-Right: 40; Altium-Bottom: 20
pins: 1, 2, 3

## S-NPN_Dup1
designator Q?
Altium-Right: 40; Altium-Bottom: 20
pins: 1, 2, 3

## SATA_DIP_0
designator J?, comment SATA_DIP_7Pin
Altium-Right: 80; Altium-Bottom: 150
pins: 1 GND1, 2 TXP, 3 TXN, 4 GND2, 5 RXN, 6 RXP, 7 GND3, 8 GND4, 9 GND5

## Sensor_MPU6500_1
designator U?
Altium-Right: 130
pins: 1 NC#1, 2 NC#2, 3 NC#3, 4 NC#4, 5 NC#5, 6 NC#6, 7 AUX_CL, 8 VDDIO, 9 SDO/AD0, 10 REGOUT, 11 FSYNC, 12 INT, 13 VDD, 14 NC#7, 15 NC#8, 16 NC#9, 17 NC#10, 18 GND, 19 RESV1, 20 RESV2, 21 AUX_DA, 22 nCS, 23 SCL/SCLK, 24 SDA/SDI, 25 E-PAD

## SIM-SPPN08-XO-1X80_0
designator J?
Altium-Right: 120; Altium-Bottom: 100
footprint SIM-SPPN08-XO-1X80
pins: 1 VCC, 2 RST, 3 CLK, 4 VPP, 5 GND, 6 I/O, 7 DATA0, 8 MCMD, 9 CART_DET, 10 GND, 11 GND, 12 GND, 13 GND

## SIM-SPPN08-XO-1X80_1
designator J?
Altium-Right: 120; Altium-Bottom: 100
footprint SIM-SPPN08-XO-1X80
pins: 1 VCC, 2 GND, 3 RST, 4 VPP, 5 CLK, 6 I/O, 7 DATA0, 8 MCMD, 9 CART_DET, 10 GND, 11 GND, 12 GND, 13 GND

## SIP7M2_0
designator J?, comment SIP7M2  (value not drawn)
PARTS: 1; OriginalSymbolOrigin: (10,130); CODE: 184999; PKG_TYPE: 9; LEVEL: STD; DEVICE: 67491-1032; Altium-Right: 40; Altium-Bottom: 120
pins: 1 P1, 2 P2, 3 P3, 4 P4, 5 P5, 6 P6, 7 P7, 8 M1, 9 M2

## SMB137B_0
designator U?
Altium-Right: 100; Altium-Bottom: 290
pins: A1 DCIN, A2 DCIN, A3 DCIN, A4 THERM, A5 EN, A6 SCL, B1 FETDRV, B2 VOUT, B3 VOUT, B4 VOUTL, B5 SDA, B6 STAT, C1 OTG/LBR, C2 USBIN, C3 SW, C4 SW, C5 SW, C6 USB5/1/HC, D1 NC, D2 USBIN, D3 GND, D4 GND, D5 GND, D6 CSOUT, E1 AUXPWR, E2 USBIN, E3 CSIN, E4 D+, E5 D-, E6 CSOUT

## SMB347_0
designator U?
Altium-Right: 100; Altium-Bottom: 250
footprint BGA30-3X2.5
pins: A1 USBIN, A2 MIDUSBIN, A3 SW, A4 MIDDCIN, A5 DCIN, B1 USBIN, B2 BOOT, B3 SW, B4 VCHG, B5 DCIN, C1 VDDCAP, C2 FETDRV, C3 THERM, C4 EN, C5 GND, D1 D-, D2 USB5/1/HC, D3 SUSP, D4 VSYS, D5 VSYS, E1 D+, E2 CHG_DET, E3 VBATT, E4 CHGOUT, E5 CHGOUT, F1 OTG/ID, F2 SCL, F3 SDA, F4 GND, F5 STAT

## SMB347_1
designator U?
Altium-Right: 100; Altium-Bottom: 250
footprint BGA30-3X2.5
pins: A1 USBIN, A2 MIDUSBIN, A3 SW, A4 MIDDCIN, A5 DCIN, B1 USBIN, B2 BOOT, B3 SW, B4 VCHG, B5 DCIN, C1 VDDCAP, C2 FETDRV, C3 THERM, C4 EN, C5 GND, D1 D-, D2 USB5/1/HC, D3 SUSP, D4 VSYS, D5 VSYS, E1 D+, E2 CHG_DET, E3 VBATT, E4 CHGOUT, E5 CHGOUT, F1 OTG/ID, F2 SCL, F3 SDA, F4 GND, F5 STAT

## SW4P_0
designator SW?
Altium-Right: 30
pins: 1, 2, 3, 4

## SW-K2-1109DE-C4SW-01
designator SW?
Altium-Right: 50; Altium-Bottom: 30
pins: 1, 2, 3

## TitleBlock1
designator *  Page Modify Date: Monday,June 3,2019  Doc: Modify note  RevCode: 1.0  Title: QIMING-RK3399  Page Size: A  Page Number: 34  Page Count: 1  (hidden comment: *)  (graphical)
Altium-Right: 455; Altium-Bottom: 91

## TP-TEST
designator TP?
Part Number: CAD; Altium-Right: 10; Altium-Bottom: 20
footprint smd_tp_1mm
pins: 1

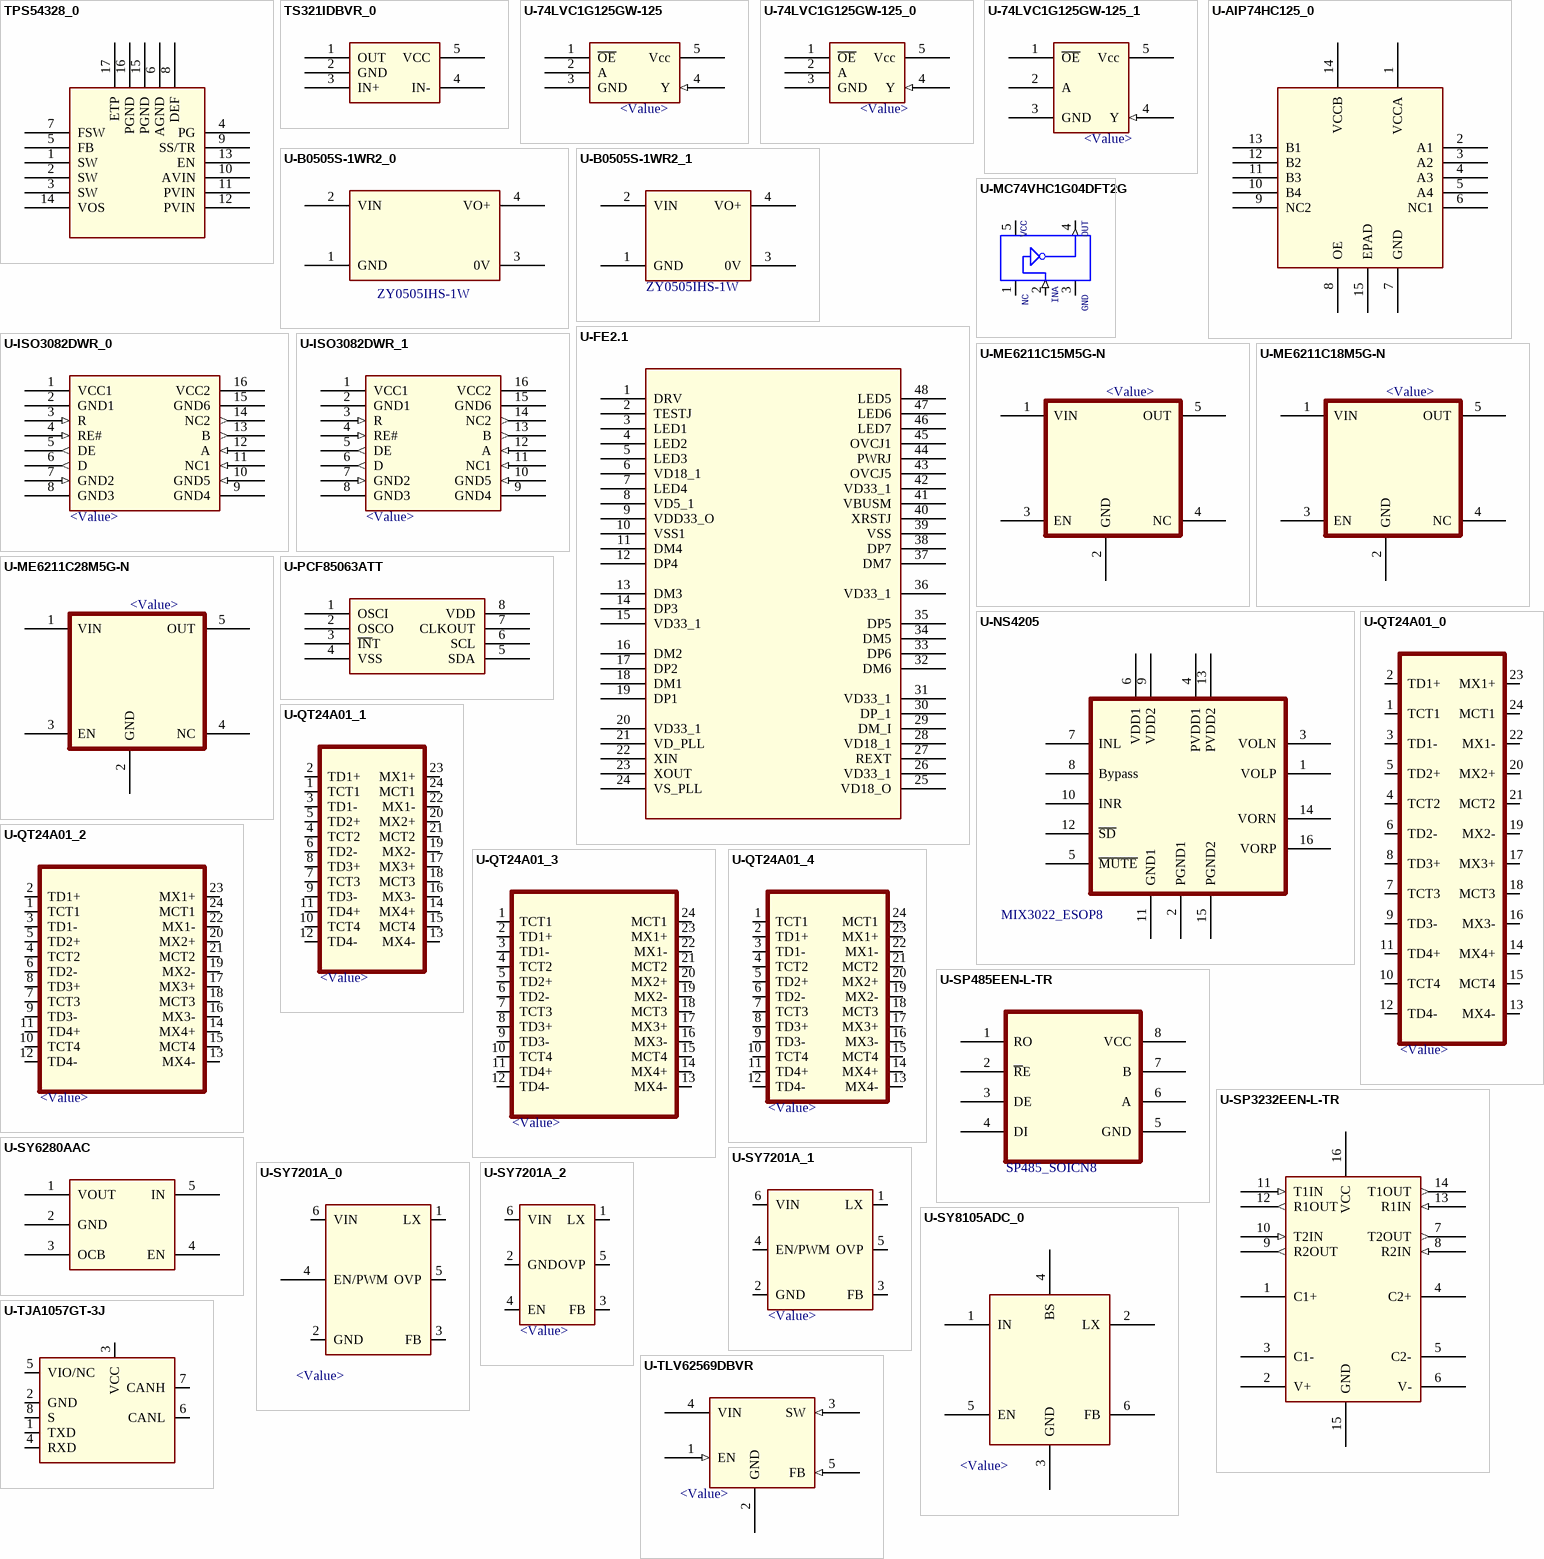
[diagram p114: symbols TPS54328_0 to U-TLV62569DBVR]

## TPS54328_0
designator U?
Altium-Right: 90; Altium-Bottom: 100
footprint SOP8A
pins: 1 SW, 2 SW, 3 SW, 4 PG, 5 FB, 6 AGND, 7 FSW, 8 DEF, 9 SS/TR, 10 AVIN, 11 PVIN, 12 PVIN, 13 EN, 14 VOS, 15 PGND, 16 PGND, 17 ETP

## TS321IDBVR_0
designator U?
Altium-Right: 60; Altium-Bottom: 40
footprint SOT25
pins: 1 OUT, 2 GND, 3 IN+, 4 IN-, 5 VCC

## U-74LVC1G125GW-125
designator U?, comment <Value>
Altium-Right: 60; Altium-Bottom: 40
pins: 1 ~{OE}, 2 A (power), 3 GND, 4 Y (in), 5 Vcc

## U-74LVC1G125GW-125_0
designator U?, comment <Value>
Altium-Right: 50; Altium-Bottom: 40
pins: 1 ~{OE}, 2 A (power), 3 GND, 4 Y (in), 5 Vcc

## U-74LVC1G125GW-125_1
designator U?, comment <Value>
Altium-Right: 50; Altium-Bottom: 60
pins: 1 ~{OE}, 2 A (power), 3 GND, 4 Y (in), 5 Vcc

## U-AIP74HC125_0
designator U?
Altium-Right: 110; Altium-Bottom: 120
pins: 1 VCCA, 2 A1, 3 A2, 4 A3, 5 A4, 6 NC1, 7 GND, 8 OE, 9 NC2, 10 B4, 11 B3, 12 B2, 13 B1, 14 VCCB, 15 EPAD

## U-B0505S-1WR2_0
designator U?, comment ZY0505IHS-1W
Altium-Right: 100; Altium-Bottom: 60
pins: 1 GND, 2 VIN, 3 0V, 4 VO+

## U-B0505S-1WR2_1
designator U?, comment ZY0505IHS-1W
Altium-Right: 70; Altium-Bottom: 60
pins: 1 GND, 2 VIN, 3 0V, 4 VO+

## U-FE2.1
designator U?
Altium-Right: 170; Altium-Bottom: 300
pins: 1 DRV, 2 TESTJ, 3 LED1, 4 LED2, 5 LED3, 6 VD18_1 (power), 7 LED4, 8 VD5_1, 9 VDD33_O, 10 VSS1, 11 DM4, 12 DP4, 13 DM3, 14 DP3, 15 VD33_1 (power), 16 DM2, 17 DP2, 18 DM1, 19 DP1, 20 VD33_1 (power), 21 VD_PLL, 22 XIN, 23 XOUT, 24 VS_PLL, 25 VD18_O, 26 VD33_1 (power), 27 REXT, 28 VD18_1 (power), 29 DM_I, 30 DP_1, 31 VD33_1 (power), 32 DM6, 33 DP6, 34 DM5, 35 DP5, 36 VD33_1 (power), 37 DM7, 38 DP7, 39 VSS, 40 XRSTJ, 41 VBUSM, 42 VD33_1 (power), 43 OVCJ5, 44 PWRJ, 45 OVCJ1, 46 LED7, 47 LED6, 48 LED5

## U-ISO3082DWR_0
designator U?, comment <Value>
Altium-Right: 100; Altium-Bottom: 90
pins: 1 VCC1 (power), 2 GND1 (power), 3 R (in), 4 RE# (in), 5 DE (out), 6 D (out), 7 GND2 (in), 8 GND3 (power), 9 GND4 (power), 10 GND5 (in), 11 NC1 (in), 12 A (in), 13 B (out), 14 NC2 (out), 15 GND6 (power), 16 VCC2 (power)

## U-ISO3082DWR_1
designator U?, comment <Value>
Altium-Right: 90
pins: 1 VCC1 (power), 2 GND1 (power), 3 R (in), 4 RE# (in), 5 DE (out), 6 D (out), 7 GND2 (in), 8 GND3 (power), 9 GND4 (power), 10 GND5 (in), 11 NC1 (in), 12 A (in), 13 B (out), 14 NC2 (out), 15 GND6 (power), 16 VCC2 (power)

## U-MC74VHC1G04DFT2G
designator U?
Altium-Right: 60; Altium-Bottom: 30
pins: 1 NC, 2 (in), 3 G, 4 (out), 5 V

## U-ME6211C15M5G-N
designator U?, comment <Value>
Altium-Right: 90
pins: 1 VIN, 2 GND, 3 EN, 4 NC, 5 OUT

## U-ME6211C18M5G-N
designator U?, comment <Value>
Altium-Right: 90
pins: 1 VIN, 2 GND, 3 EN, 4 NC, 5 OUT

## U-ME6211C28M5G-N
designator U?, comment <Value>
Altium-Right: 90
pins: 1 VIN, 2 GND, 3 EN, 4 NC, 5 OUT

## U-NS4205
designator U?, comment MIX3022_ESOP8
Altium-Right: 130
pins: 1 VOLP, 2 PGND1, 3 VOLN, 4 PVDD1, 5 ~{MUTE}, 6 VDD1, 7 INL, 8 Bypass, 9 VDD2, 10 INR, 11 GND1, 12 ~{SD}, 13 PVDD2, 14 VORN, 15 PGND2, 16 VORP

## U-PCF85063ATT
designator U?
Altium-Right: 90; Altium-Bottom: 50
pins: 1 OSCI, 2 OSCO, 3 ~{IN}T, 4 VSS, 5 SDA, 6 SCL, 7 CLKOUT, 8 VDD

## U-QT24A01_0
designator U?, comment <Value>
Altium-Right: 70; Altium-Bottom: 260
pins: 1 TCT1, 2 TD1+, 3 TD1-, 4 TCT2, 5 TD2+, 6 TD2-, 7 TCT3, 8 TD3+, 9 TD3-, 10 TCT4, 11 TD4+, 12 TD4-, 13 MX4-, 14 MX4+, 15 MCT4, 16 MX3-, 17 MX3+, 18 MCT3, 19 MX2-, 20 MX2+, 21 MCT2, 22 MX1-, 23 MX1+, 24 MCT1

## U-QT24A01_1
designator U?, comment <Value>
Altium-Right: 70; Altium-Bottom: 150
pins: 1 TCT1, 2 TD1+, 3 TD1-, 4 TCT2, 5 TD2+, 6 TD2-, 7 TCT3, 8 TD3+, 9 TD3-, 10 TCT4, 11 TD4+, 12 TD4-, 13 MX4-, 14 MX4+, 15 MCT4, 16 MX3-, 17 MX3+, 18 MCT3, 19 MX2-, 20 MX2+, 21 MCT2, 22 MX1-, 23 MX1+, 24 MCT1

## U-QT24A01_2
designator U?, comment <Value>
Altium-Right: 110; Altium-Bottom: 150
pins: 1 TCT1, 2 TD1+, 3 TD1-, 4 TCT2, 5 TD2+, 6 TD2-, 7 TCT3, 8 TD3+, 9 TD3-, 10 TCT4, 11 TD4+, 12 TD4-, 13 MX4-, 14 MX4+, 15 MCT4, 16 MX3-, 17 MX3+, 18 MCT3, 19 MX2-, 20 MX2+, 21 MCT2, 22 MX1-, 23 MX1+, 24 MCT1

## U-QT24A01_3
designator U?, comment <Value>
Altium-Right: 110; Altium-Bottom: 150
pins: 1 TCT1, 2 TD1+, 3 TD1-, 4 TCT2, 5 TD2+, 6 TD2-, 7 TCT3, 8 TD3+, 9 TD3-, 10 TCT4, 11 TD4+, 12 TD4-, 13 MX4-, 14 MX4+, 15 MCT4, 16 MX3-, 17 MX3+, 18 MCT3, 19 MX2-, 20 MX2+, 21 MCT2, 22 MX1-, 23 MX1+, 24 MCT1

## U-QT24A01_4
designator U?, comment <Value>
Altium-Right: 80; Altium-Bottom: 140
pins: 1 TCT1, 2 TD1+, 3 TD1-, 4 TCT2, 5 TD2+, 6 TD2-, 7 TCT3, 8 TD3+, 9 TD3-, 10 TCT4, 11 TD4+, 12 TD4-, 13 MX4-, 14 MX4+, 15 MCT4, 16 MX3-, 17 MX3+, 18 MCT3, 19 MX2-, 20 MX2+, 21 MCT2, 22 MX1-, 23 MX1+, 24 MCT1

## U-SP485EEN-L-TR
designator U?, comment SP485_SOICN8
Altium-Right: 90; Altium-Bottom: 100
pins: 1 RO, 2 ~{R}E, 3 DE, 4 DI, 5 GND, 6 A, 7 B, 8 VCC

## U-SP3232EEN-L-TR
designator U?
Altium-Right: 90; Altium-Bottom: 150
pins: 1 C1+, 2 V+, 3 C1-, 4 C2+, 5 C2-, 6 V-, 7 T2OUT (out), 8 R2IN (in), 9 R2OUT (out), 10 T2IN (in), 11 T1IN (in), 12 R1OUT (out), 13 R1IN (in), 14 T1OUT (out), 15 GND (power), 16 VCC (power)

## U-SY6280AAC
designator U?
Altium-Right: 70; Altium-Bottom: 60
pins: 1 VOUT, 2 GND, 3 OCB, 4 EN, 5 IN

## U-SY7201A_0
designator U?, comment <Value>
Altium-Right: 70; Altium-Bottom: 100
pins: 1 LX, 2 GND, 3 FB, 4 EN/PWM, 5 OVP, 6 VIN

## U-SY7201A_1
designator U?, comment <Value>
Altium-Right: 70; Altium-Bottom: 80
pins: 1 LX, 2 GND, 3 FB, 4 EN/PWM, 5 OVP, 6 VIN

## U-SY7201A_2
designator U?, comment <Value>
Altium-Right: 50; Altium-Bottom: 80
pins: 1 LX, 2 GND, 3 FB, 4 EN, 5 OVP, 6 VIN

## U-SY8105ADC_0
designator U?, comment <Value>
Altium-Right: 80; Altium-Bottom: 100
pins: 1 IN, 2 LX, 3 GND, 4 BS, 5 EN, 6 FB

## U-TJA1057GT-3J
designator U?
Altium-Right: 90; Altium-Bottom: 70
pins: 1 TXD, 2 GND (power), 3 VCC (power), 4 RXD, 5 VIO/NC, 6 CANL, 7 CANH, 8 S

## U-TLV62569DBVR
designator U?, comment <Value>
Altium-Right: 70; Altium-Bottom: 60
pins: 1 EN (in), 2 GND (power), 3 SW (in), 4 VIN (power), 5 FB (in)

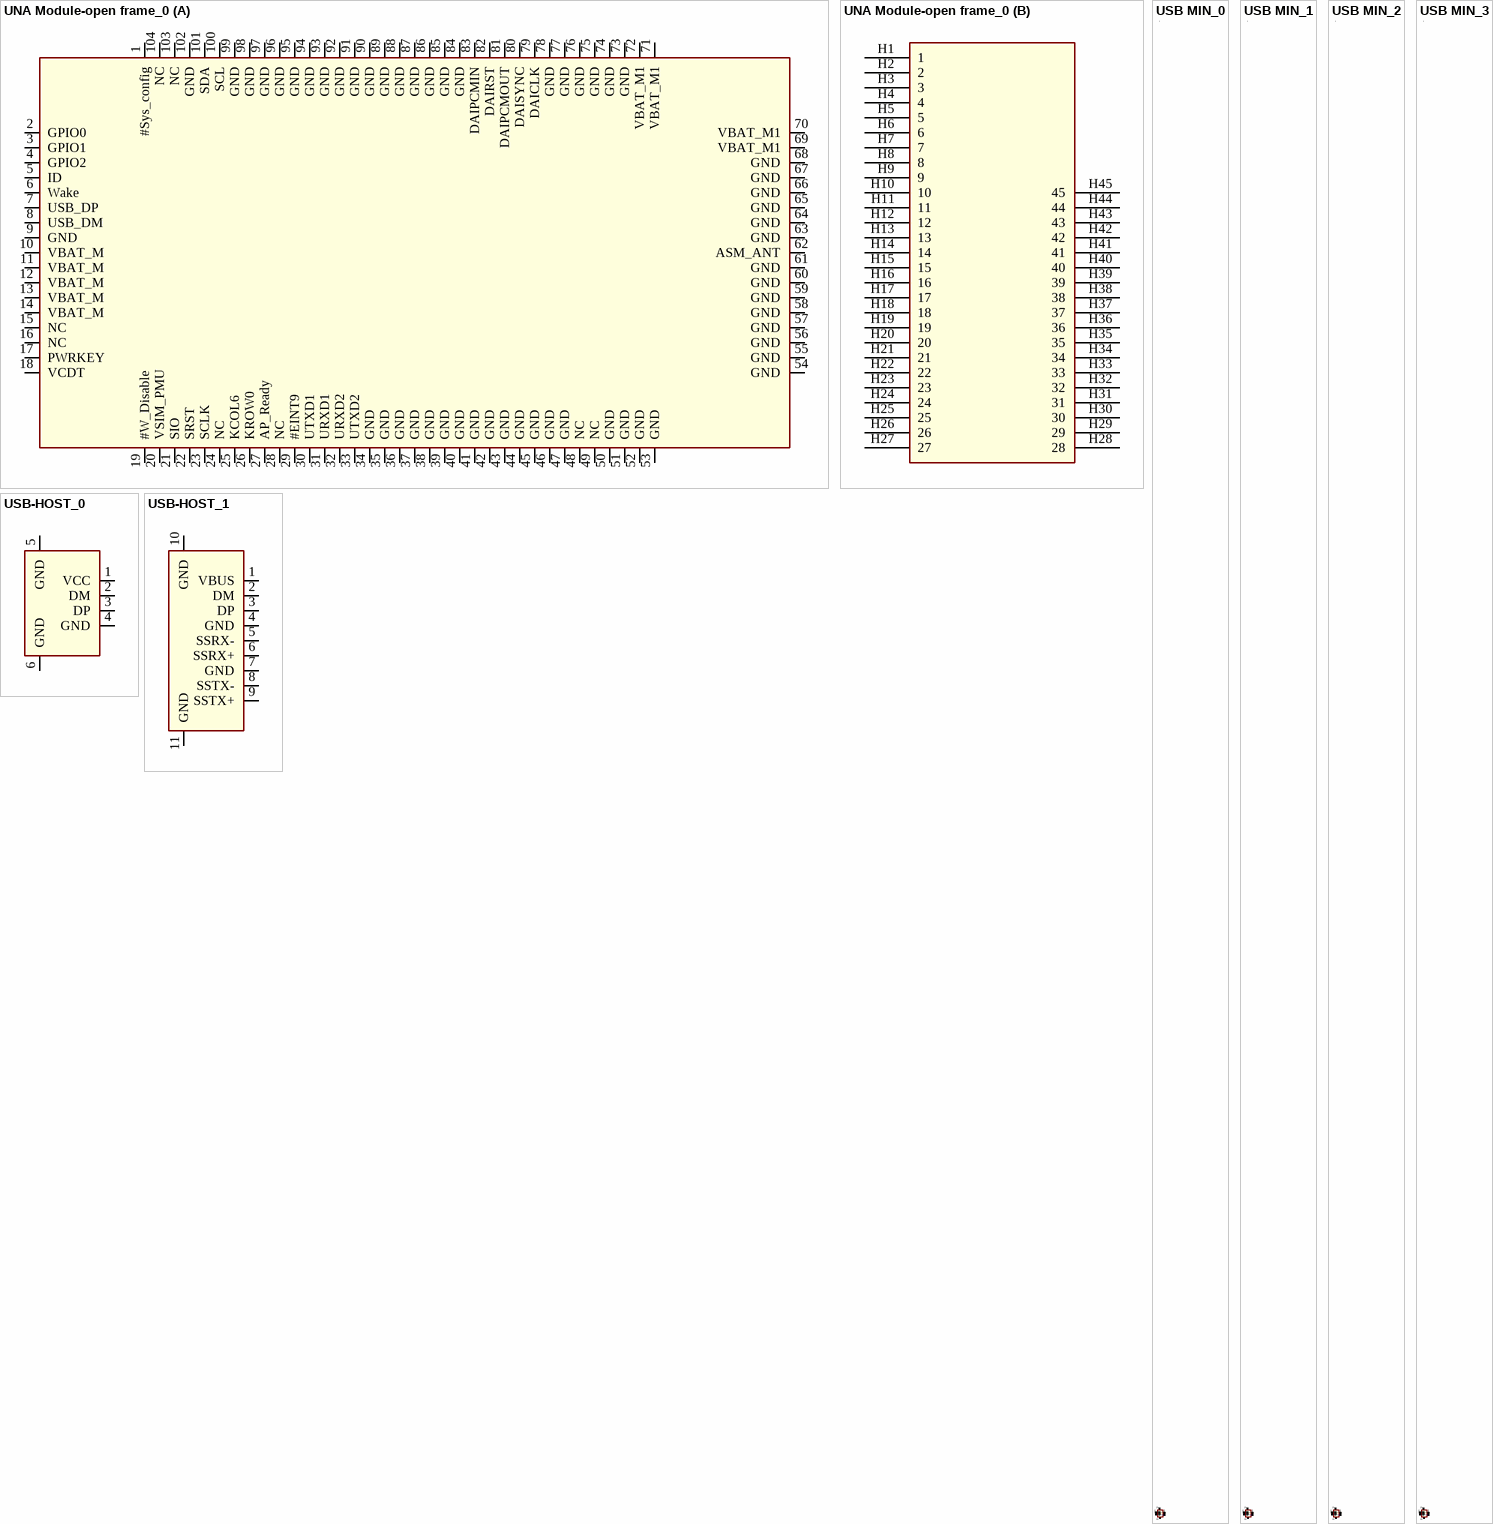
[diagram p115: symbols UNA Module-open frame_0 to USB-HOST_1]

## UNA Module-open frame_0
designator U?
Altium-Right: 500; Altium-Bottom: 260; Altium-Right1: 110; Altium-Bottom1: 280
part A pins: 1 #Sys_config, 2 GPIO0, 3 GPIO1, 4 GPIO2, 5 ID, 6 Wake, 7 USB_DP, 8 USB_DM, 9 GND, 10 VBAT_M, 11 VBAT_M, 12 VBAT_M, 13 VBAT_M, 14 VBAT_M, 15 NC, 16 NC, 17 PWRKEY, 18 VCDT, 19 #W_Disable, 20 VSIM_PMU, 21 SIO, 22 SRST, 23 SCLK, 24 NC, 25 KCOL6, 26 KROW0, 27 AP_Ready, 28 NC, 29 #EINT9, 30 UTXD1, 31 URXD1, 32 URXD2, 33 UTXD2, 34 GND, 35 GND, 36 GND, 37 GND, 38 GND, 39 GND, 40 GND, 41 GND, 42 GND, 43 GND, 44 GND, 45 GND, 46 GND, 47 GND, 48 NC, 49 NC, 50 GND, 51 GND, 52 GND, 53 GND, 54 GND, 55 GND, 56 GND, 57 GND, 58 GND, 59 GND, 60 GND, 61 GND, 62 ASM_ANT, 63 GND, 64 GND, 65 GND, 66 GND, 67 GND, 68 GND, 69 VBAT_M1, 70 VBAT_M1, 71 VBAT_M1, 72 VBAT_M1, 73 GND, 74 GND, 75 GND, 76 GND, 77 GND, 78 GND, 79 DAICLK, 80 DAISYNC, 81 DAIPCMOUT, 82 DAIRST, 83 DAIPCMIN, 84 GND, 85 GND, 86 GND, 87 GND, 88 GND, 89 GND, 90 GND, 91 GND, 92 GND, 93 GND, 94 GND, 95 GND, 96 GND, 97 GND, 98 GND, 99 GND, 100 SCL, 101 SDA, 102 GND, 103 NC, 104 NC
part B pins: H1 1, H2 2, H3 3, H4 4, H5 5, H6 6, H7 7, H8 8, H9 9, H10 10, H11 11, H12 12, H13 13, H14 14, H15 15, H16 16, H17 17, H18 18, H19 19, H20 20, H21 21, H22 22, H23 23, H24 24, H25 25, H26 26, H27 27, H28 28, H29 29, H30 30, H31 31, H32 32, H33 33, H34 34, H35 35, H36 36, H37 37, H38 38, H39 39, H40 40, H41 41, H42 42, H43 43, H44 44, H45 45

## USB MIN_0
designator J?, comment USBmin
Altium-Right: 80; Altium-Bottom: 90
pins: 1 NC, 2 VBUS, 3 TD_DM, 4 DM, 5 NC (power), 6 DP, 7 NC, 8 ID, 9 NC, 10 GND, 11 GND, 12 GND, 13 GND, 14 GND

## USB MIN_1
designator J?, comment USBmin
Altium-Right: 80; Altium-Bottom: 90
pins: 1 NC, 2 VBUS, 3 TD_DM, 4 DM, 5 NC (power), 6 DP, 7 NC, 8 ID, 9 NC, 10 GND, 11 GND, 12 GND, 13 GND, 14 GND

## USB MIN_2
designator J?, comment USBmin
Altium-Right: 80; Altium-Bottom: 90
pins: 1 NC, 2 VBUS, 3 TD_DM, 4 DM, 5 NC, 6 DP, 7 NC, 8 ID, 9 NC, 10 GND, 11 GND, 12 GND, 13 GND, 14 GND

## USB MIN_3
designator J?, comment USBmin
Altium-Right: 80; Altium-Bottom: 90
pins: 1 NC, 2 VBUS, 3 TD_DM, 4 DM, 5 NC, 6 DP, 7 NC, 8 ID, 9 NC, 10 GND, 11 GND, 12 GND, 13 GND, 14 GND

## USB-HOST_0
designator J?
Altium-Right: 50; Altium-Bottom: 70
footprint USB-HOST
pins: 1 VCC, 2 DM, 3 DP, 4 GND, 5 GND, 6 GND

## USB-HOST_1
designator J?
Altium-Right: 50; Altium-Bottom: 120
footprint USB-HOST
pins: 1 VBUS, 2 DM, 3 DP, 4 GND, 5 SSRX-, 6 SSRX+, 7 GND, 8 SSTX-, 9 SSTX+, 10 GND, 11 GND

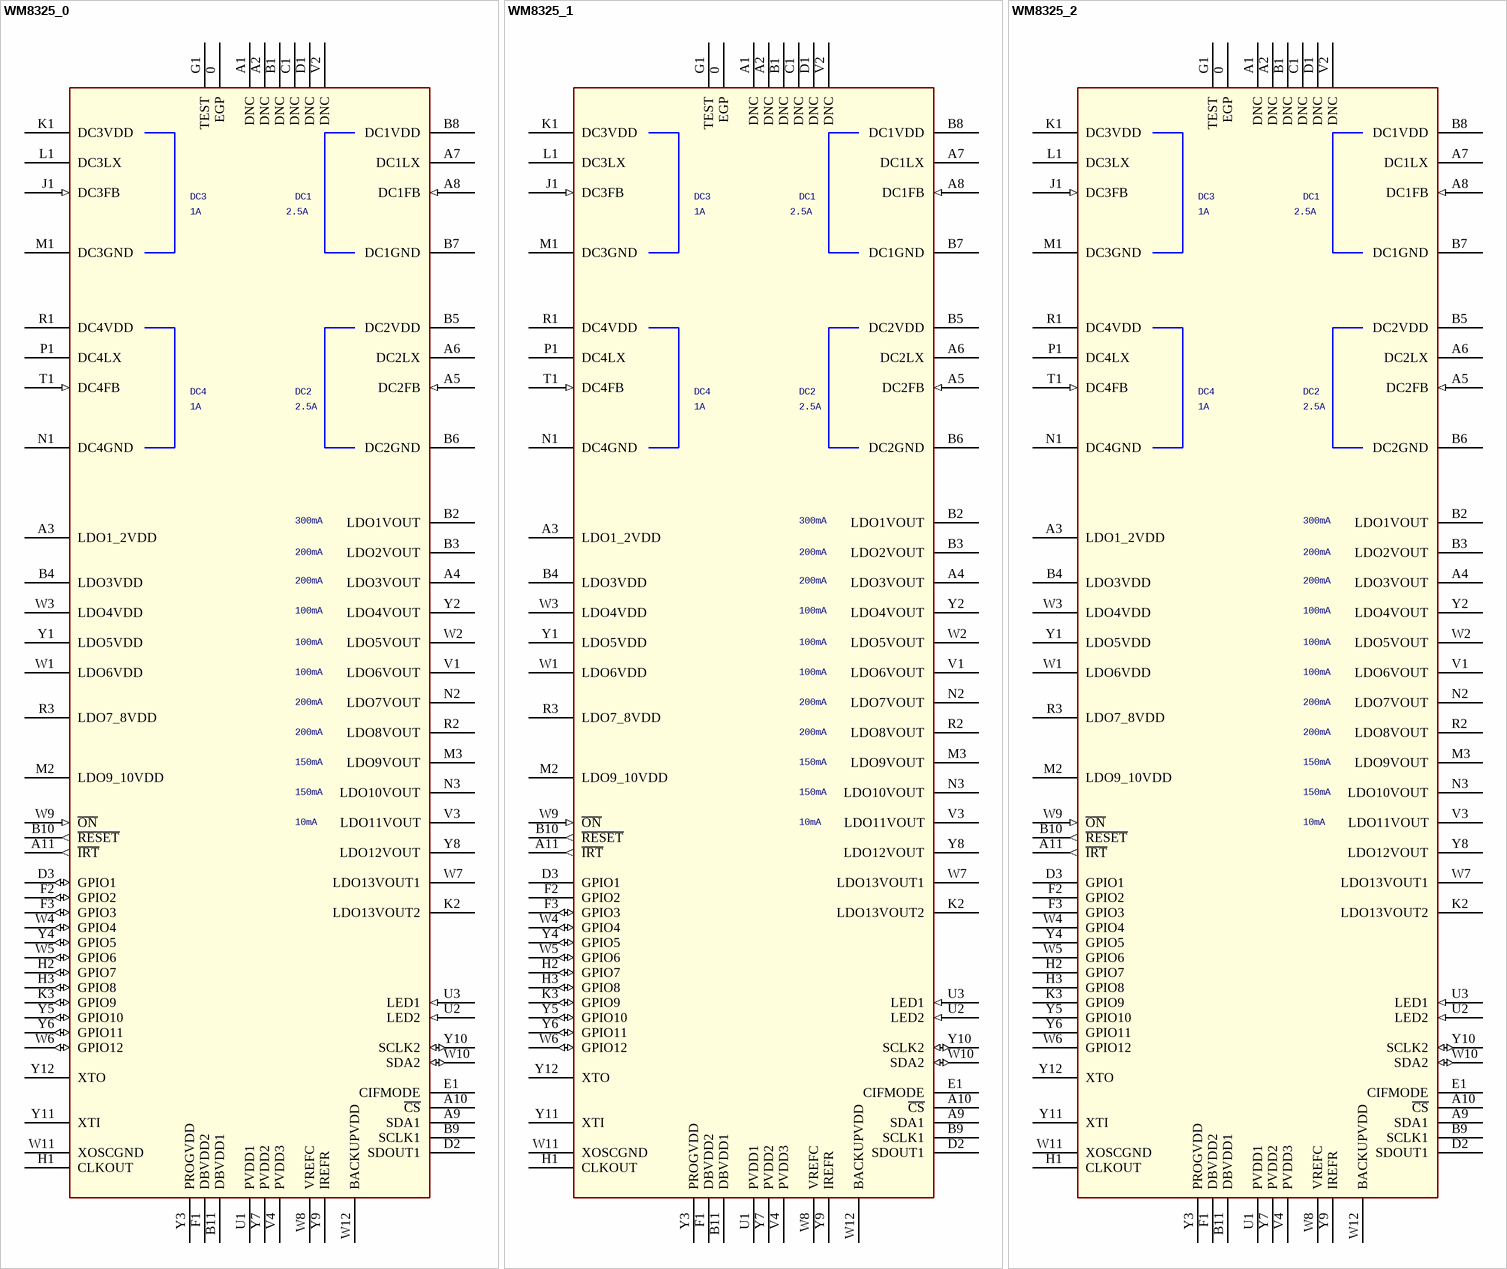
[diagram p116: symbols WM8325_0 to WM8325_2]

## WM8325_0
designator U?
Altium-Right: 240; Altium-Bottom: 740
footprint QFN81-8X8
pins: 0 EGP, A1 DNC, A2 DNC, A3 LDO1_2VDD (power), A4 LDO3VOUT (power), A5 DC2FB (in), A6 DC2LX (power), A7 DC1LX (power), A8 DC1FB (in), A9 SDA1, A10 ~{CS}, A11 ~{IRT} (out), B1 DNC, B2 LDO1VOUT (power), B3 LDO2VOUT (power), B4 LDO3VDD (power), B5 DC2VDD (power), B6 DC2GND (power), B7 DC1GND (power), B8 DC1VDD (power), B9 SCLK1, B10 ~{RESET} (out), B11 DBVDD1, C1 DNC, D1 DNC, D2 SDOUT1, D3 GPIO1 (io), E1 CIFMODE, F1 DBVDD2, F2 GPIO2 (io), F3 GPIO3 (io), G1 TEST, H1 CLKOUT, H2 GPIO7 (io), H3 GPIO8 (io), J1 DC3FB (in), K1 DC3VDD (power), K2 LDO13VOUT2 (power), K3 GPIO9 (io), L1 DC3LX (power), M1 DC3GND (power), M2 LDO9_10VDD (power), M3 LDO9VOUT (power), N1 DC4GND (power), N2 LDO7VOUT (power), N3 LDO10VOUT (power), P1 DC4LX (power), R1 DC4VDD (power), R2 LDO8VOUT (power), R3 LDO7_8VDD (power), T1 DC4FB (in), U1 PVDD1, U2 LED2 (in), U3 LED1 (in), V1 LDO6VOUT (power), V2 DNC, V3 LDO11VOUT (power), V4 PVDD3, W1 LDO6VDD (power), W2 LDO5VOUT (power), W3 LDO4VDD (power), W4 GPIO4 (io), W5 GPIO6 (io), W6 GPIO12 (io), W7 LDO13VOUT1 (power), W8 VREFC, W9 ~{ON} (in), W10 SDA2 (io), W11 XOSCGND, W12 BACKUPVDD, Y1 LDO5VDD (power), Y2 LDO4VOUT (power), Y3 PROGVDD, Y4 GPIO5 (io), Y5 GPIO10 (io), Y6 GPIO11 (io), Y7 PVDD2, Y8 LDO12VOUT (power), Y9 IREFR, Y10 SCLK2 (io), Y11 XTI, Y12 XTO

## WM8325_1
designator U?
Altium-Right: 240; Altium-Bottom: 740
footprint QFN81-8X8
pins: 0 EGP, A1 DNC, A2 DNC, A3 LDO1_2VDD (power), A4 LDO3VOUT (power), A5 DC2FB (in), A6 DC2LX (power), A7 DC1LX (power), A8 DC1FB (in), A9 SDA1, A10 ~{CS}, A11 ~{IRT} (out), B1 DNC, B2 LDO1VOUT (power), B3 LDO2VOUT (power), B4 LDO3VDD (power), B5 DC2VDD (power), B6 DC2GND (power), B7 DC1GND (power), B8 DC1VDD (power), B9 SCLK1, B10 ~{RESET} (out), B11 DBVDD1, C1 DNC, D1 DNC, D2 SDOUT1, D3 GPIO1, E1 CIFMODE, F1 DBVDD2, F2 GPIO2, F3 GPIO3 (io), G1 TEST, H1 CLKOUT, H2 GPIO7 (io), H3 GPIO8 (io), J1 DC3FB (in), K1 DC3VDD (power), K2 LDO13VOUT2 (power), K3 GPIO9 (io), L1 DC3LX (power), M1 DC3GND (power), M2 LDO9_10VDD (power), M3 LDO9VOUT (power), N1 DC4GND (power), N2 LDO7VOUT (power), N3 LDO10VOUT (power), P1 DC4LX (power), R1 DC4VDD (power), R2 LDO8VOUT (power), R3 LDO7_8VDD (power), T1 DC4FB (in), U1 PVDD1, U2 LED2 (in), U3 LED1 (in), V1 LDO6VOUT (power), V2 DNC, V3 LDO11VOUT (power), V4 PVDD3, W1 LDO6VDD (power), W2 LDO5VOUT (power), W3 LDO4VDD (power), W4 GPIO4 (io), W5 GPIO6 (io), W6 GPIO12 (io), W7 LDO13VOUT1 (power), W8 VREFC, W9 ~{ON} (in), W10 SDA2 (io), W11 XOSCGND, W12 BACKUPVDD, Y1 LDO5VDD (power), Y2 LDO4VOUT (power), Y3 PROGVDD, Y4 GPIO5 (io), Y5 GPIO10 (io), Y6 GPIO11 (io), Y7 PVDD2, Y8 LDO12VOUT (power), Y9 IREFR, Y10 SCLK2 (io), Y11 XTI, Y12 XTO

## WM8325_2
designator U?
Altium-Right: 240; Altium-Bottom: 740
footprint QFN81-8X8
pins: 0 EGP, A1 DNC, A2 DNC, A3 LDO1_2VDD (power), A4 LDO3VOUT (power), A5 DC2FB (in), A6 DC2LX (power), A7 DC1LX (power), A8 DC1FB (in), A9 SDA1, A10 ~{CS}, A11 ~{IRT} (out), B1 DNC, B2 LDO1VOUT (power), B3 LDO2VOUT (power), B4 LDO3VDD (power), B5 DC2VDD (power), B6 DC2GND (power), B7 DC1GND (power), B8 DC1VDD (power), B9 SCLK1, B10 ~{RESET} (out), B11 DBVDD1, C1 DNC, D1 DNC, D2 SDOUT1, D3 GPIO1, E1 CIFMODE, F1 DBVDD2, F2 GPIO2, F3 GPIO3, G1 TEST, H1 CLKOUT, H2 GPIO7, H3 GPIO8, J1 DC3FB (in), K1 DC3VDD (power), K2 LDO13VOUT2 (power), K3 GPIO9, L1 DC3LX (power), M1 DC3GND (power), M2 LDO9_10VDD (power), M3 LDO9VOUT (power), N1 DC4GND (power), N2 LDO7VOUT (power), N3 LDO10VOUT (power), P1 DC4LX (power), R1 DC4VDD (power), R2 LDO8VOUT (power), R3 LDO7_8VDD (power), T1 DC4FB (in), U1 PVDD1, U2 LED2 (in), U3 LED1 (in), V1 LDO6VOUT (power), V2 DNC, V3 LDO11VOUT (power), V4 PVDD3, W1 LDO6VDD (power), W2 LDO5VOUT (power), W3 LDO4VDD (power), W4 GPIO4, W5 GPIO6, W6 GPIO12, W7 LDO13VOUT1 (power), W8 VREFC, W9 ~{ON} (in), W10 SDA2 (io), W11 XOSCGND, W12 BACKUPVDD, Y1 LDO5VDD (power), Y2 LDO4VOUT (power), Y3 PROGVDD, Y4 GPIO5, Y5 GPIO10, Y6 GPIO11, Y7 PVDD2, Y8 LDO12VOUT (power), Y9 IREFR, Y10 SCLK2 (io), Y11 XTI, Y12 XTO

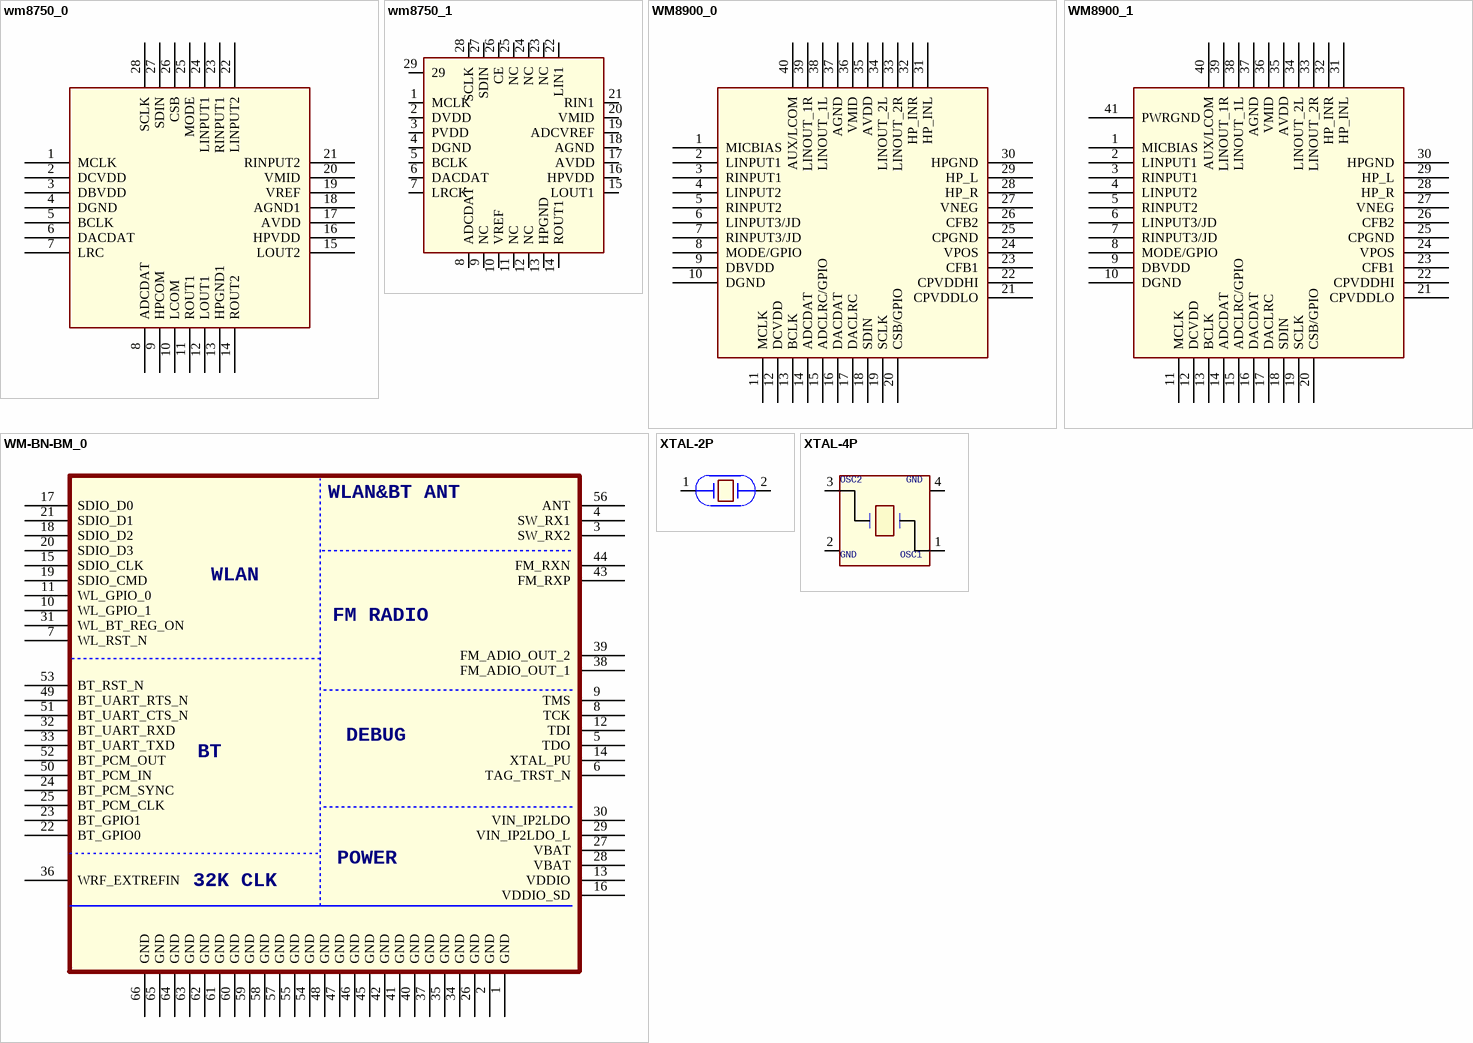
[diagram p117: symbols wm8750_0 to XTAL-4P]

## wm8750_0
designator U?
Altium-Right: 160
pins: 1 MCLK, 2 DCVDD, 3 DBVDD, 4 DGND, 5 BCLK, 6 DACDAT, 7 LRC, 8 ADCDAT, 9 HPCOM, 10 LCOM, 11 ROUT1, 12 LOUT1, 13 HPGND1, 14 ROUT2, 15 LOUT2, 16 HPVDD, 17 AVDD, 18 AGND1, 19 VREF, 20 VMID, 21 RINPUT2, 22 LINPUT2, 23 RINPUT1, 24 LINPUT1, 25 MODE, 26 CSB, 27 SDIN, 28 SCLK

## wm8750_1
designator U?
Altium-Right: 120; Altium-Bottom: 130
pins: 1 MCLK, 2 DVDD, 3 PVDD, 4 DGND, 5 BCLK, 6 DACDAT, 7 LRCK, 8 ADCDAT, 9 NC, 10 VREF, 11 NC, 12 NC, 13 HPGND, 14 ROUT1, 15 LOUT1, 16 HPVDD, 17 AVDD, 18 AGND, 19 ADCVREF, 20 VMID, 21 RIN1, 22 LIN1, 23 NC, 24 NC, 25 NC, 26 CE, 27 SDIN, 28 SCLK, 29

## WM8900_0
designator U?
Altium-Right: 180
footprint QFN40
pins: 1 MICBIAS, 2 LINPUT1, 3 RINPUT1, 4 LINPUT2, 5 RINPUT2, 6 LINPUT3/JD, 7 RINPUT3/JD, 8 MODE/GPIO, 9 DBVDD, 10 DGND, 11 MCLK, 12 DCVDD, 13 BCLK, 14 ADCDAT, 15 ADCLRC/GPIO, 16 DACDAT, 17 DACLRC, 18 SDIN, 19 SCLK, 20 CSB/GPIO, 21 CPVDDLO, 22 CPVDDHI, 23 CFB1, 24 VPOS, 25 CPGND, 26 CFB2, 27 VNEG, 28 HP_R, 29 HP_L, 30 HPGND, 31 HP_INL, 32 HP_INR, 33 LINOUT_2R, 34 LINOUT_2L, 35 AVDD, 36 VMID, 37 AGND, 38 LINOUT_1L, 39 LINOUT_1R, 40 AUX/LCOM

## WM8900_1
designator U?
Altium-Right: 180
footprint QFN40
pins: 1 MICBIAS, 2 LINPUT1, 3 RINPUT1, 4 LINPUT2, 5 RINPUT2, 6 LINPUT3/JD, 7 RINPUT3/JD, 8 MODE/GPIO, 9 DBVDD, 10 DGND, 11 MCLK, 12 DCVDD, 13 BCLK, 14 ADCDAT, 15 ADCLRC/GPIO, 16 DACDAT, 17 DACLRC, 18 SDIN, 19 SCLK, 20 CSB/GPIO, 21 CPVDDLO, 22 CPVDDHI, 23 CFB1, 24 VPOS, 25 CPGND, 26 CFB2, 27 VNEG, 28 HP_R, 29 HP_L, 30 HPGND, 31 HP_INL, 32 HP_INR, 33 LINOUT_2R, 34 LINOUT_2L, 35 AVDD, 36 VMID, 37 AGND, 38 LINOUT_1L, 39 LINOUT_1R, 40 AUX/LCOM, 41 PWRGND

## WM-BN-BM_0
designator U?
Altium-Right: 340; Altium-Bottom: 331
footprint LGA66
pins: 1 GND, 2 GND, 3 SW_RX2, 4 SW_RX1, 5 TDO, 6 TAG_TRST_N, 7 WL_RST_N, 8 TCK, 9 TMS, 10 WL_GPIO_1, 11 WL_GPIO_0, 12 TDI, 13 VDDIO, 14 XTAL_PU, 15 SDIO_CLK, 16 VDDIO_SD, 17 SDIO_D0, 18 SDIO_D2, 19 SDIO_CMD, 20 SDIO_D3, 21 SDIO_D1, 22 BT_GPIO0, 23 BT_GPIO1, 24 BT_PCM_SYNC, 25 BT_PCM_CLK, 26 GND, 27 VBAT, 28 VBAT, 29 VIN_IP2LDO_L, 30 VIN_IP2LDO, 31 WL_BT_REG_ON, 32 BT_UART_RXD, 33 BT_UART_TXD, 34 GND, 35 GND, 36 WRF_EXTREFIN, 37 GND, 38 FM_ADIO_OUT_1, 39 FM_ADIO_OUT_2, 40 GND, 41 GND, 42 GND, 43 FM_RXP, 44 FM_RXN, 45 GND, 46 GND, 47 GND, 48 GND, 49 BT_UART_RTS_N, 50 BT_PCM_IN, 51 BT_UART_CTS_N, 52 BT_PCM_OUT, 53 BT_RST_N, 54 GND, 55 GND, 56 ANT, 57 GND, 58 GND, 59 GND, 60 GND, 61 GND, 62 GND, 63 GND, 64 GND, 65 GND, 66 GND

## XTAL-2P
designator XT?
CLASS: IC; Altium-Right: 40; Altium-Bottom: 20
pins: 1, 2

## XTAL-4P
designator XT?
CLASS: IC; Altium-Right: 60
pins: 1, 2, 3, 4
